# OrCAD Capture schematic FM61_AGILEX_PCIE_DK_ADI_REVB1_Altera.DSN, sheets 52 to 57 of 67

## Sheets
52 PWR - VCC -2: size Custom
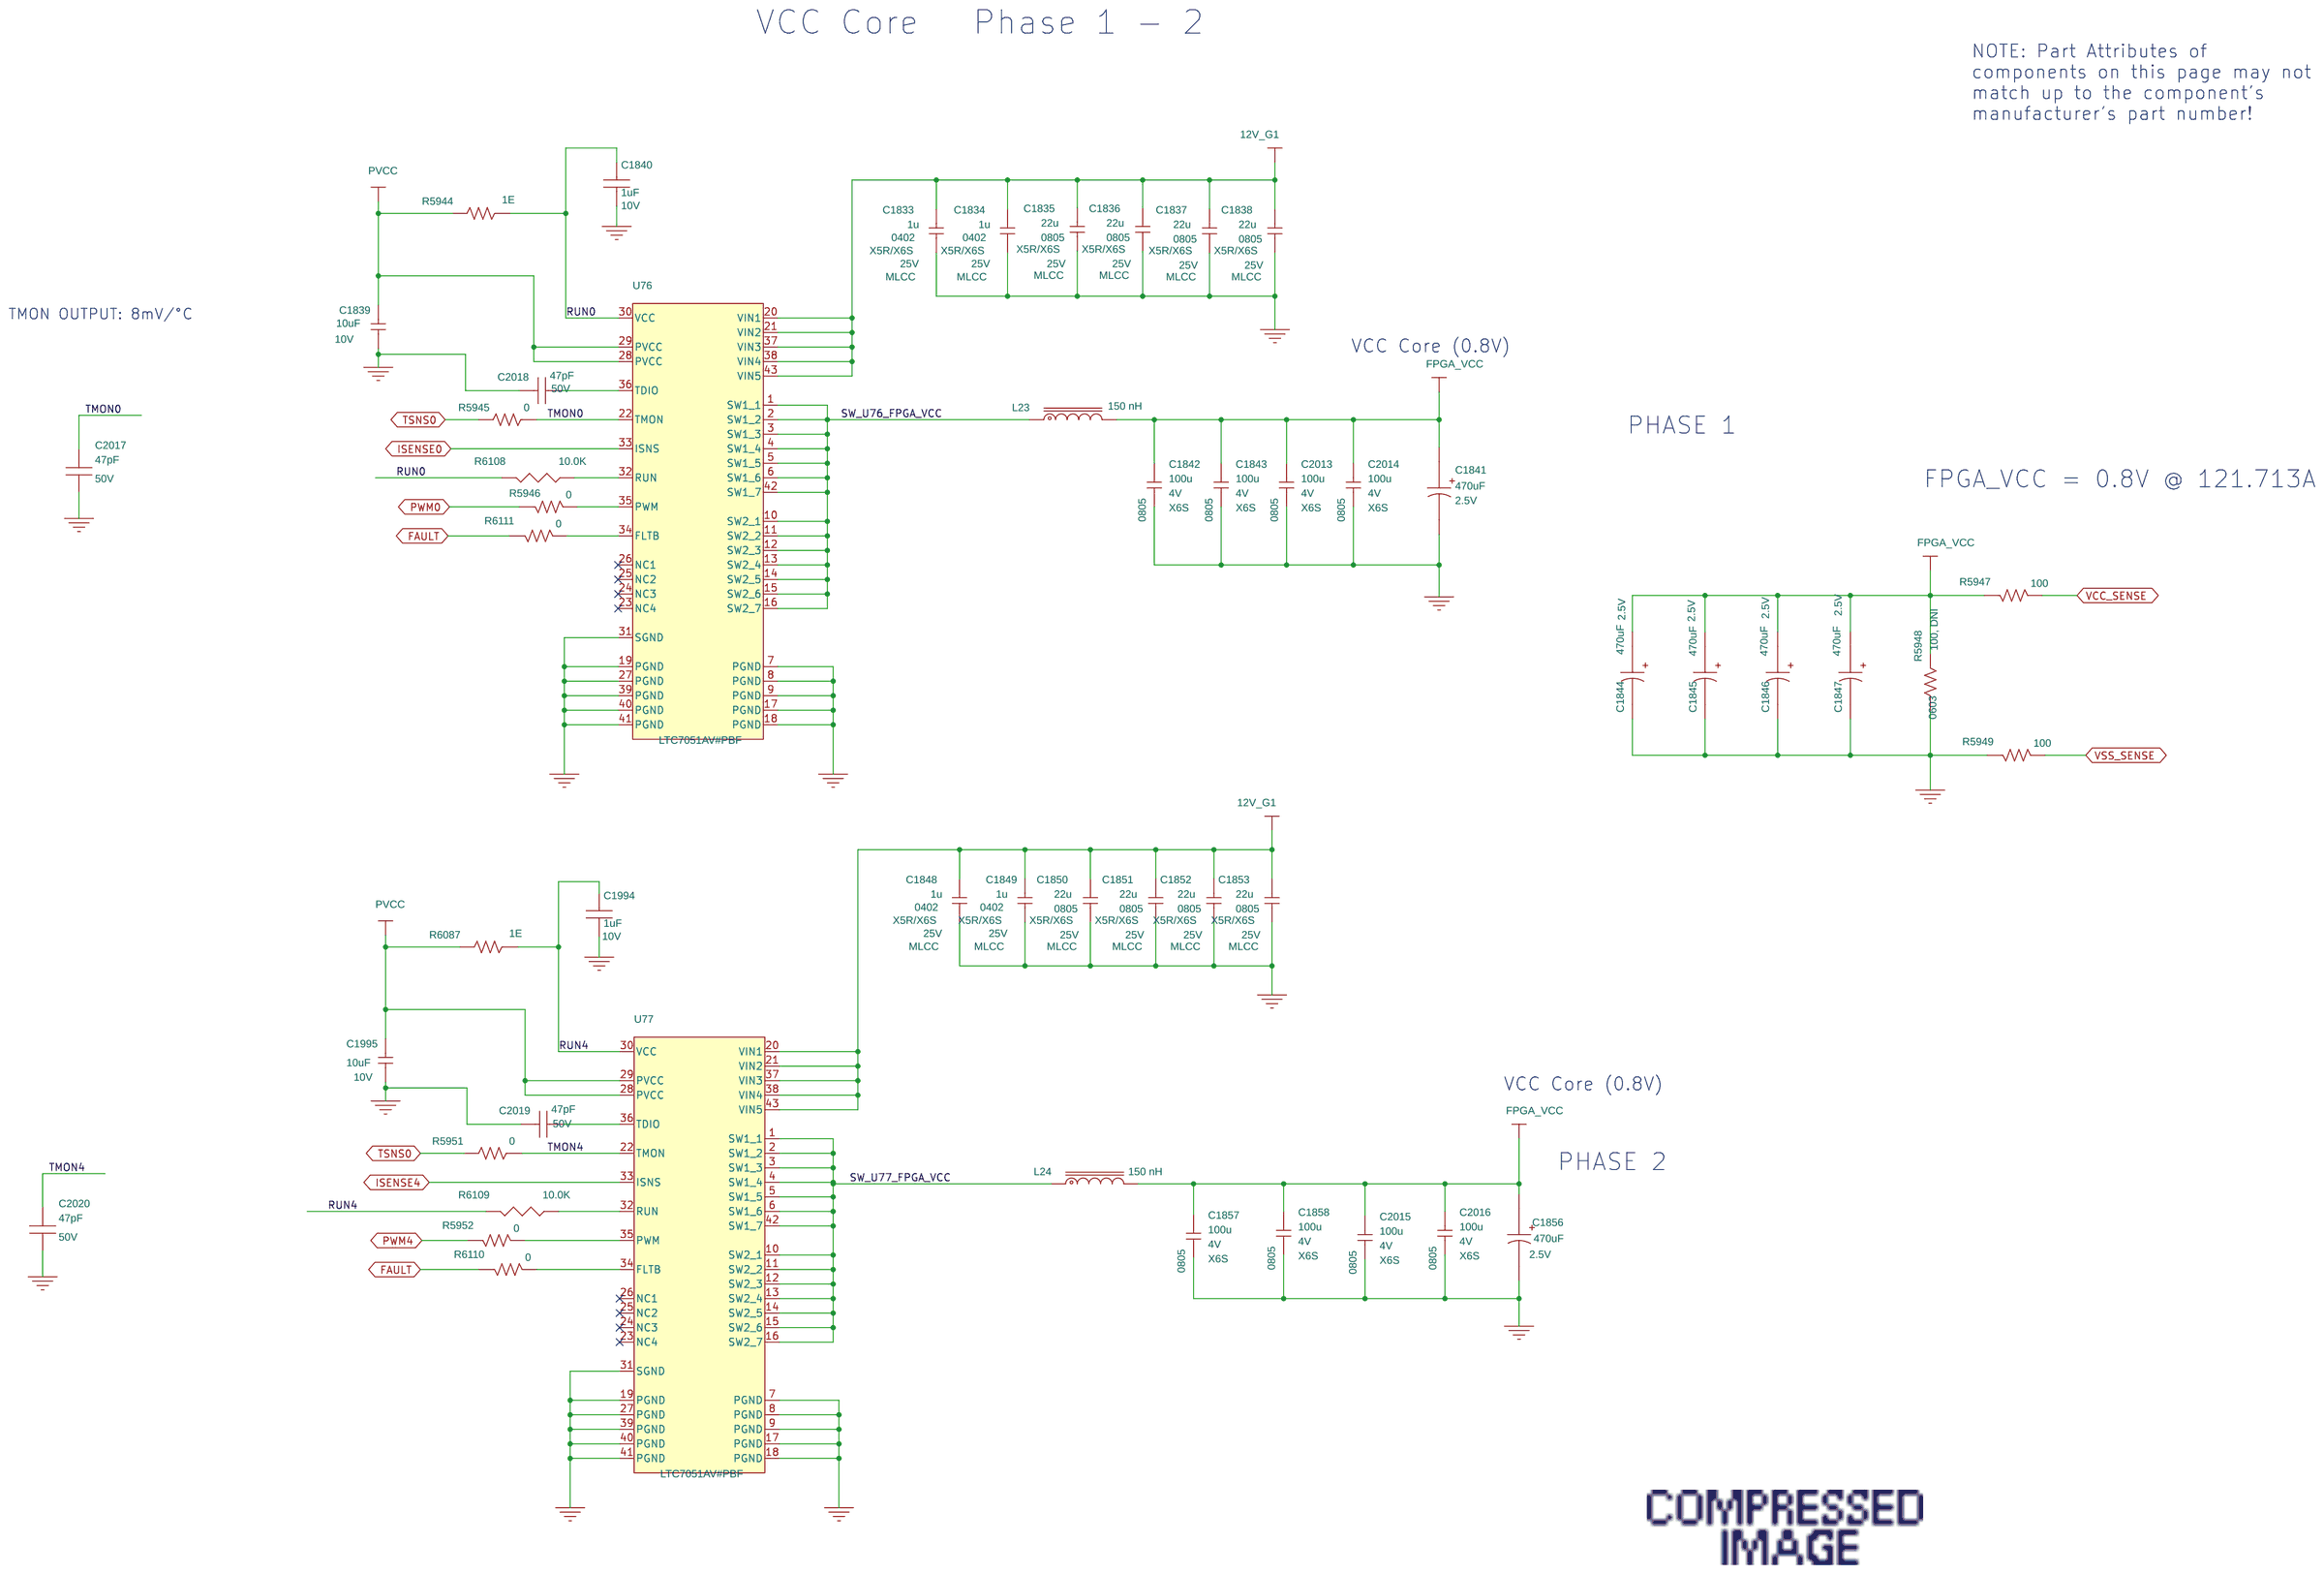
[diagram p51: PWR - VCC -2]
53 PWR - VCC -3: size Custom
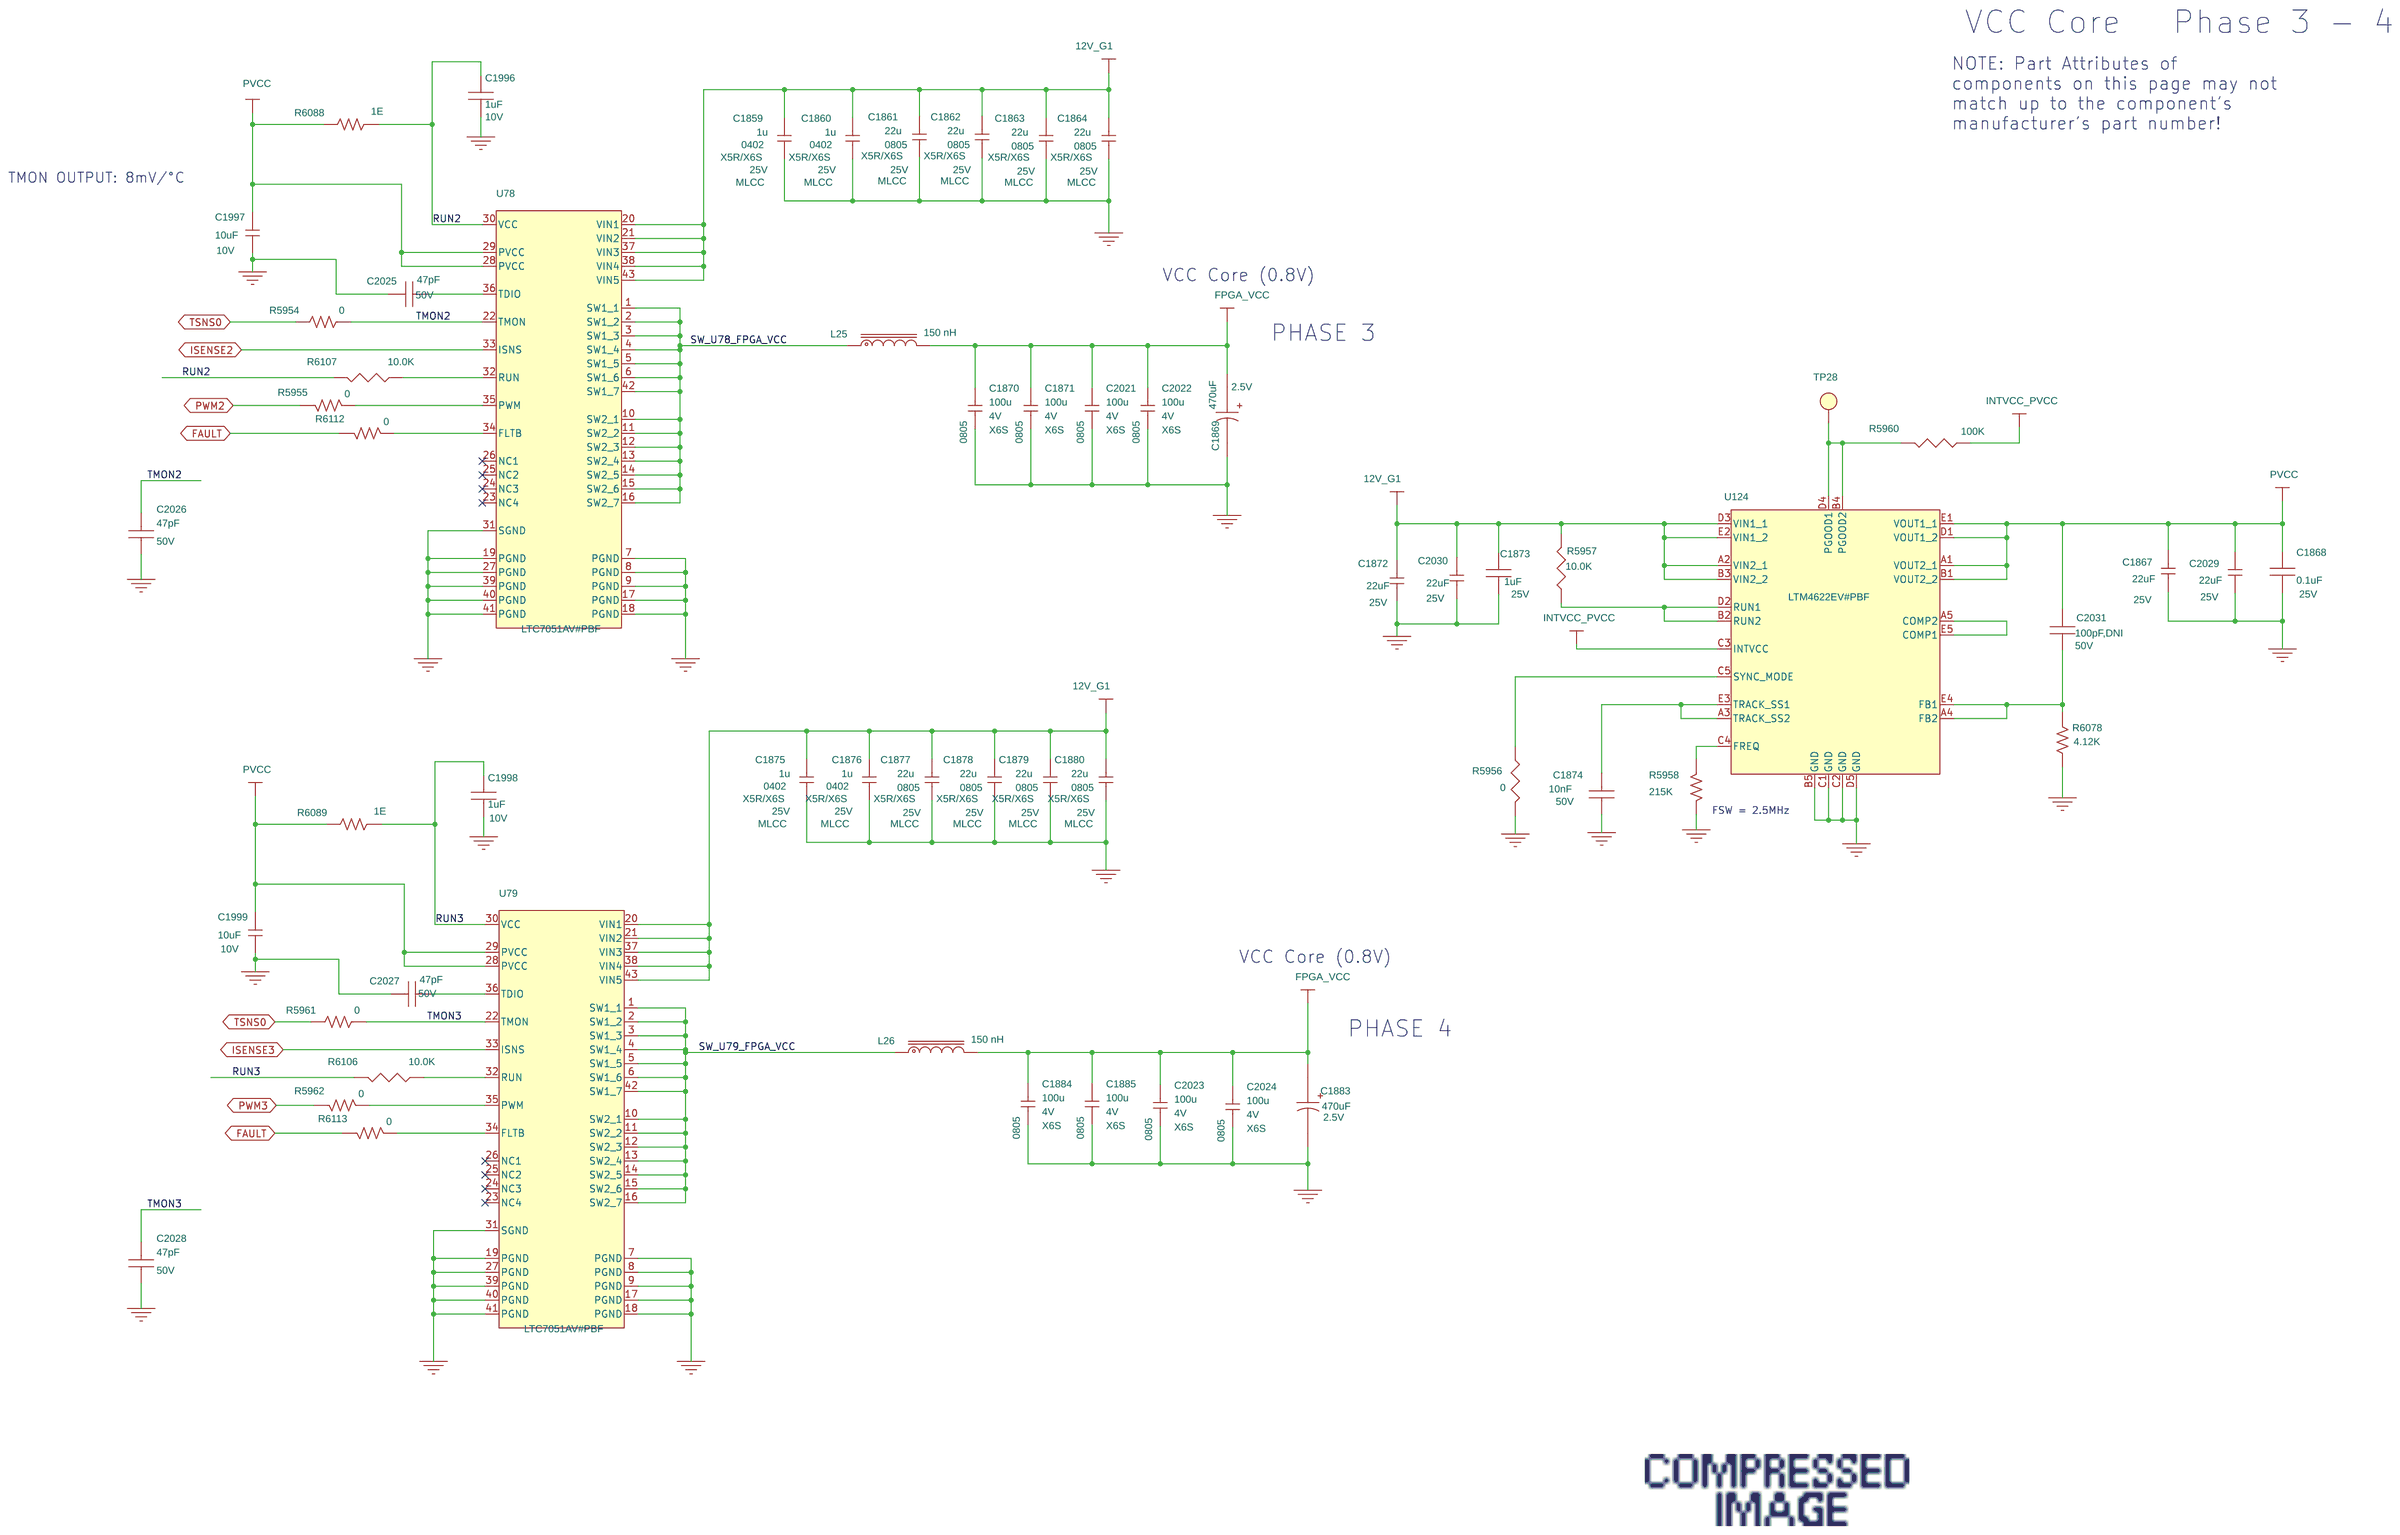
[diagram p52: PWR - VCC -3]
54 PWR - 1p8V: size Custom
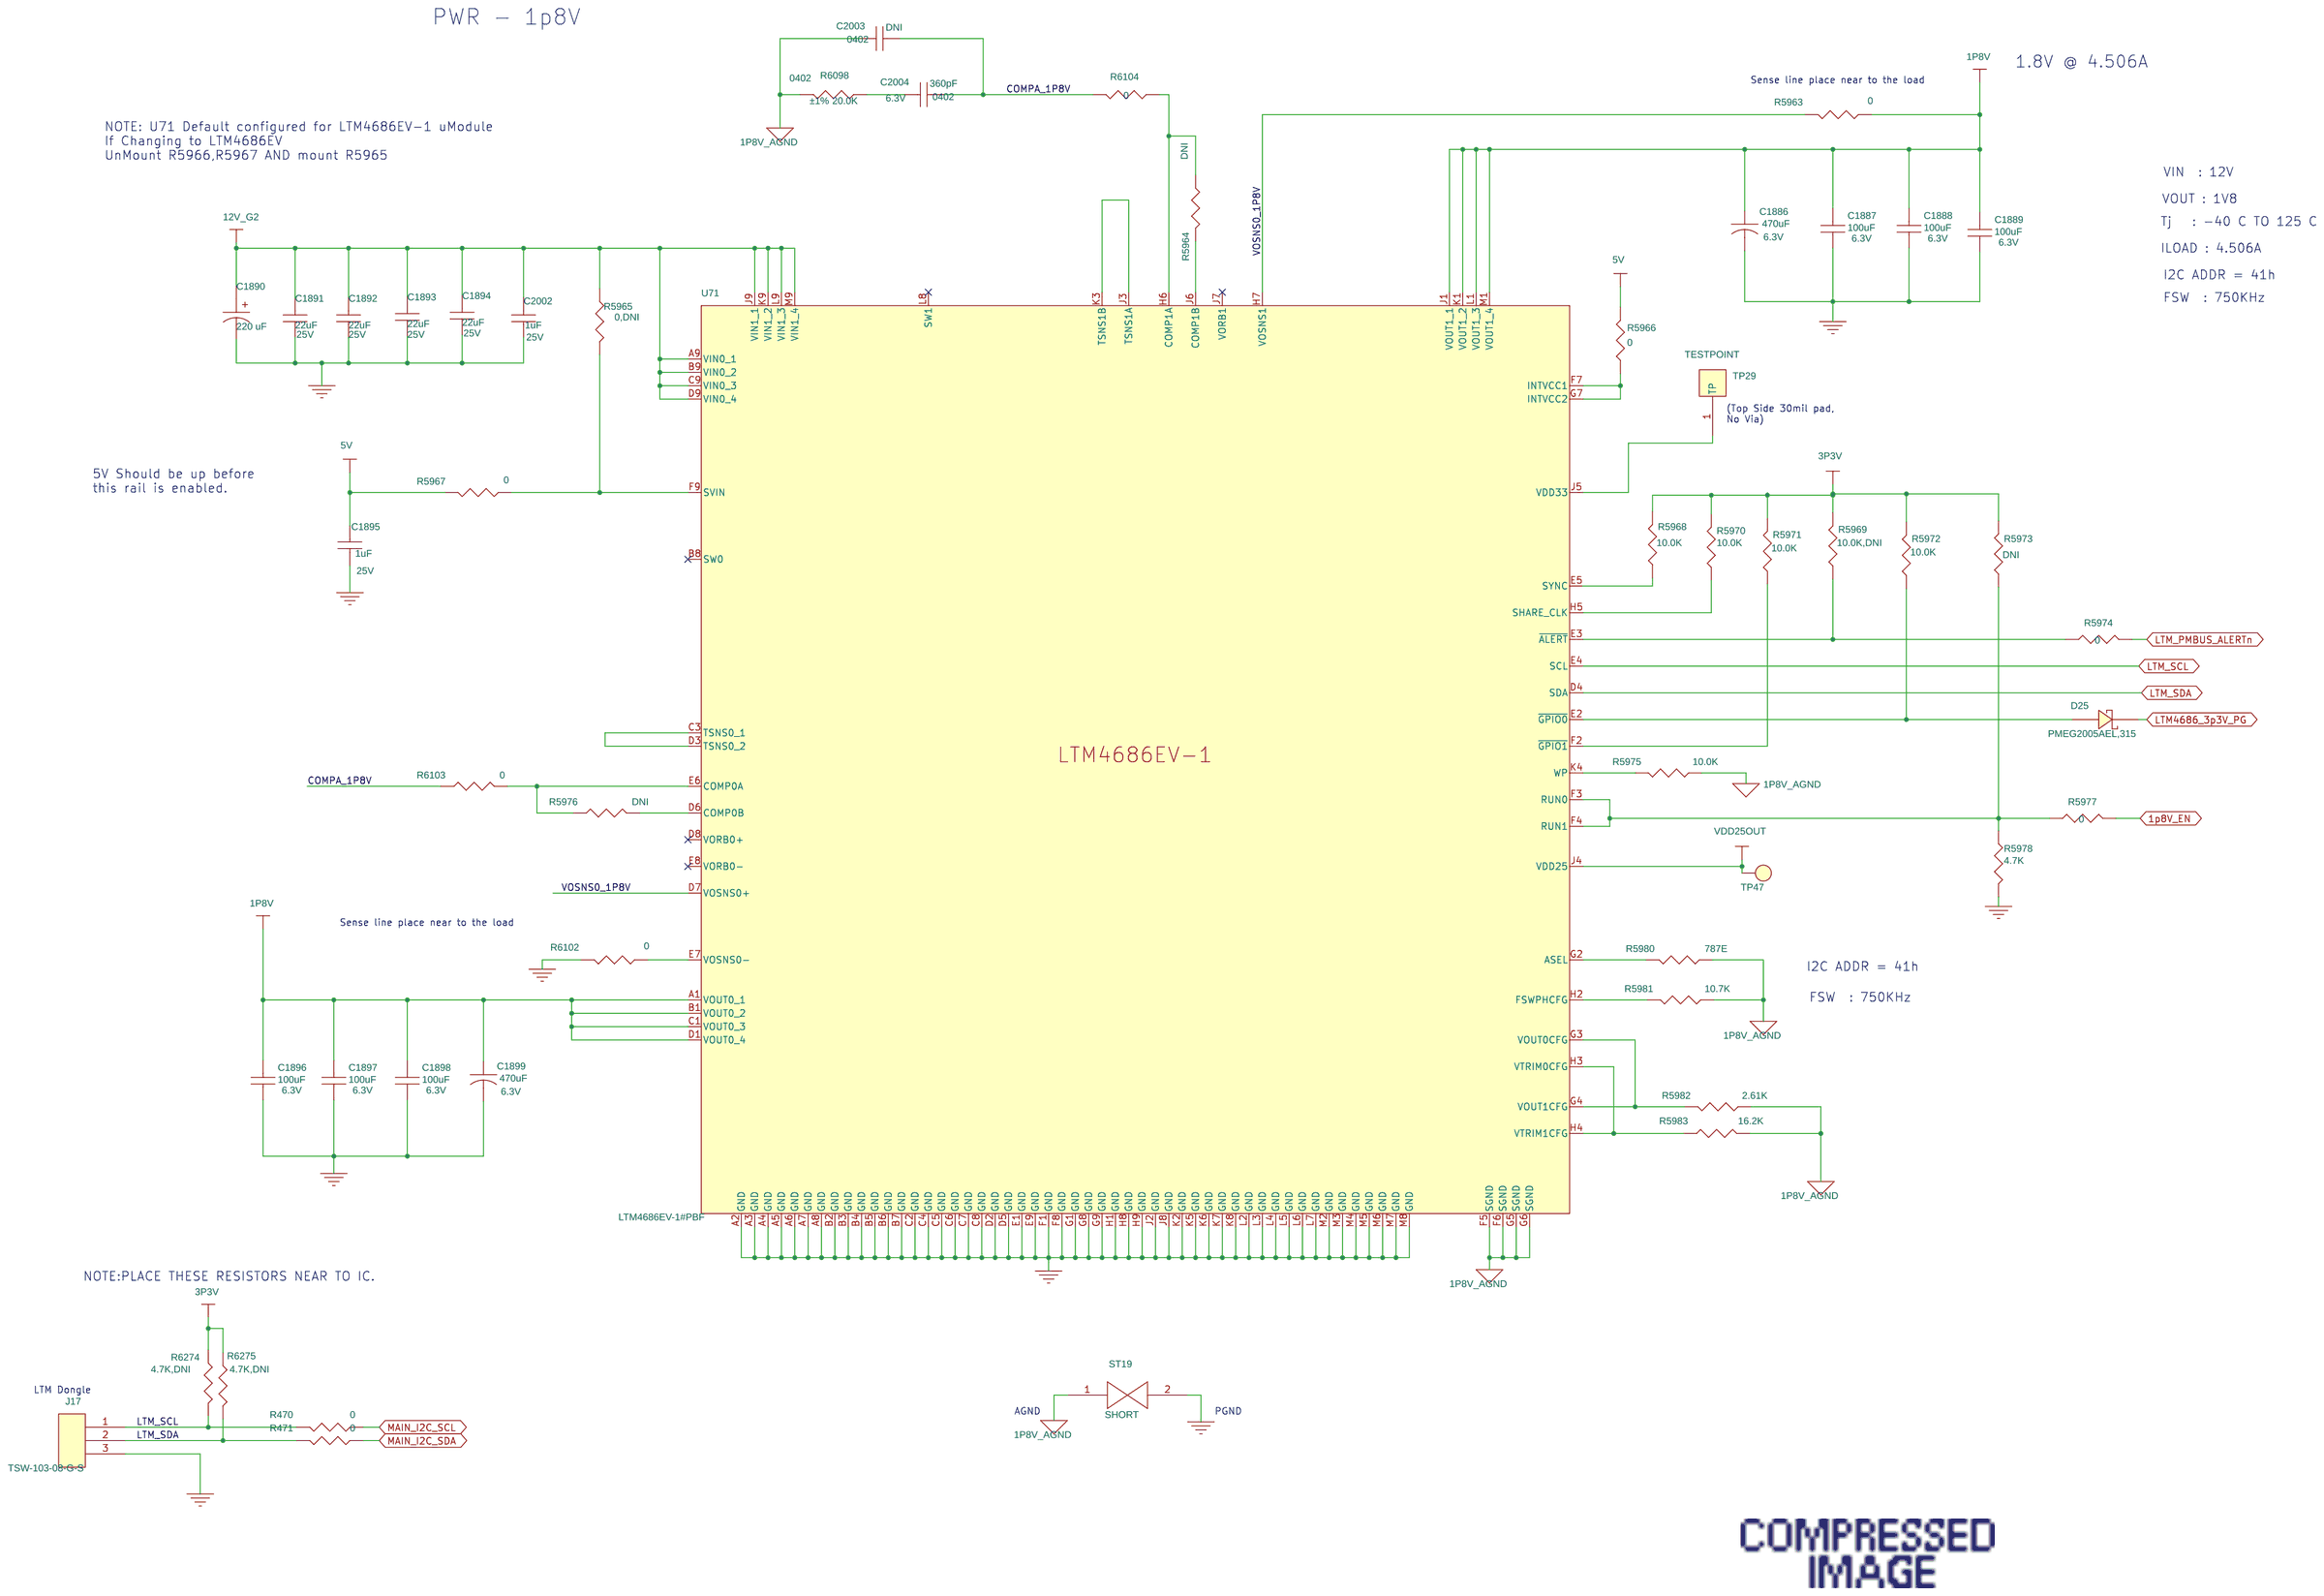
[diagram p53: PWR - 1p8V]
55 PWR - 0p8V_VCCL_SDM: size B
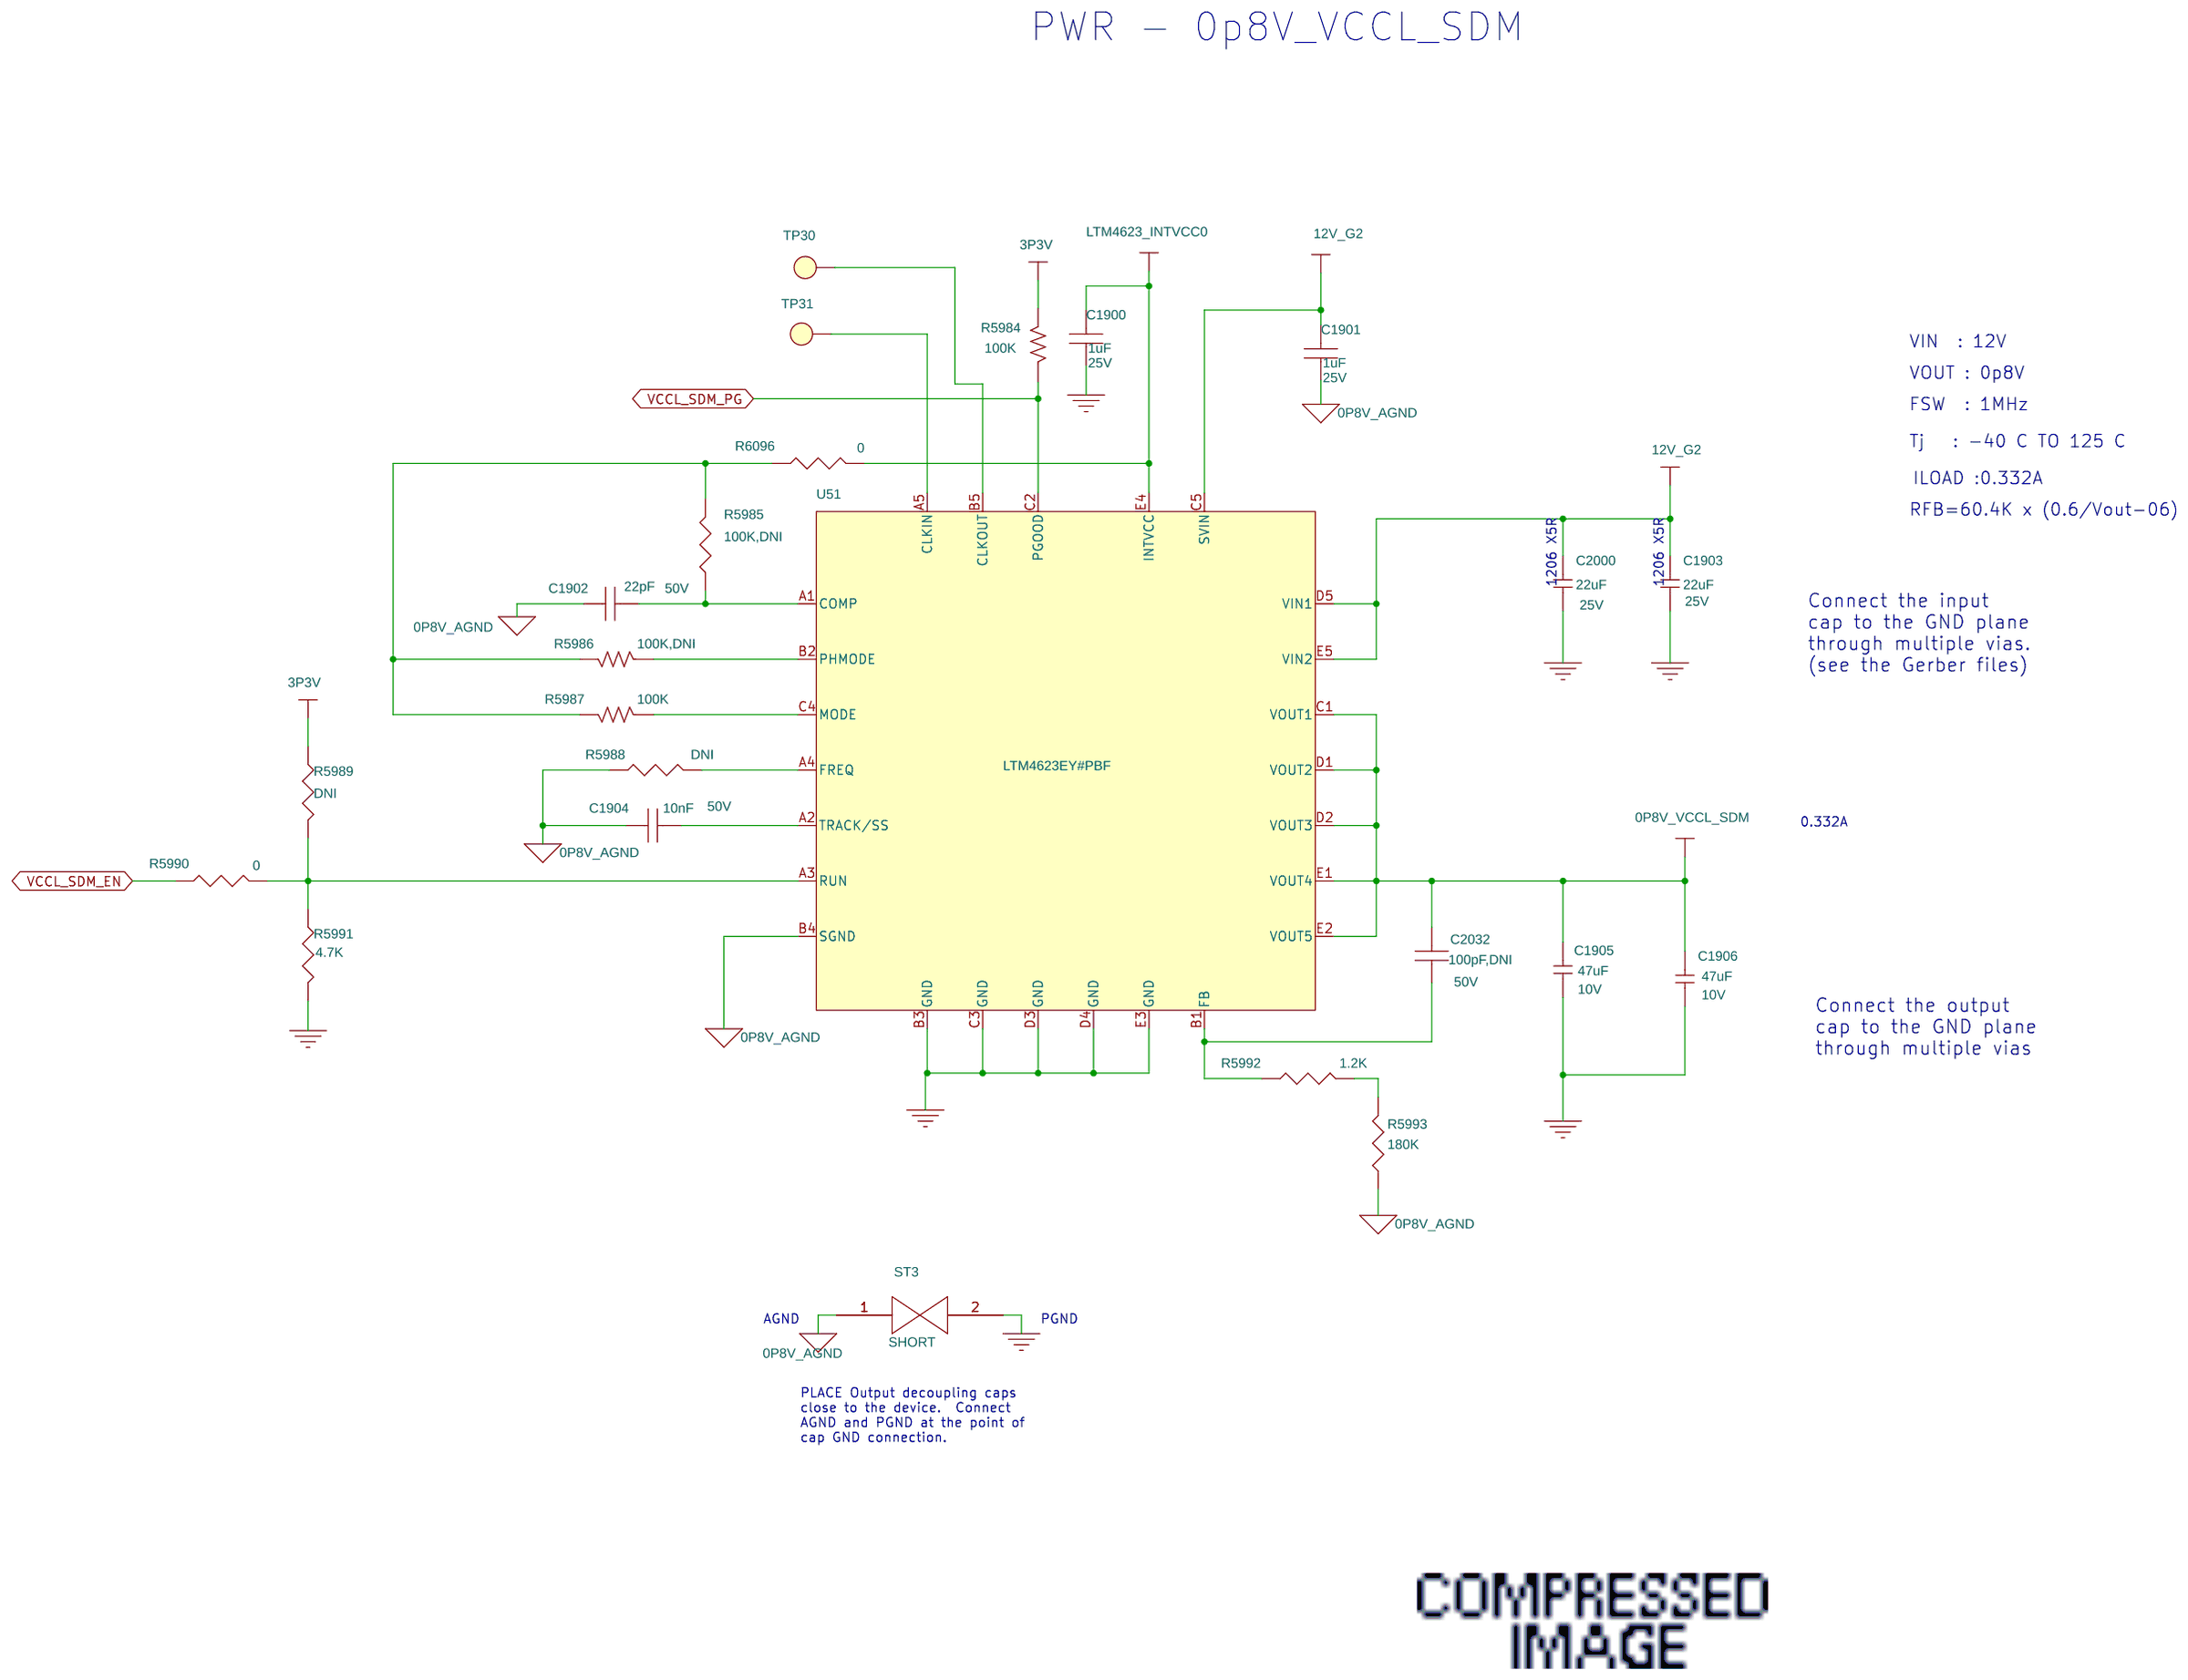
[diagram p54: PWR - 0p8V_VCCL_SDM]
56 PWR - 0p9V_VCCL_HPS: size B
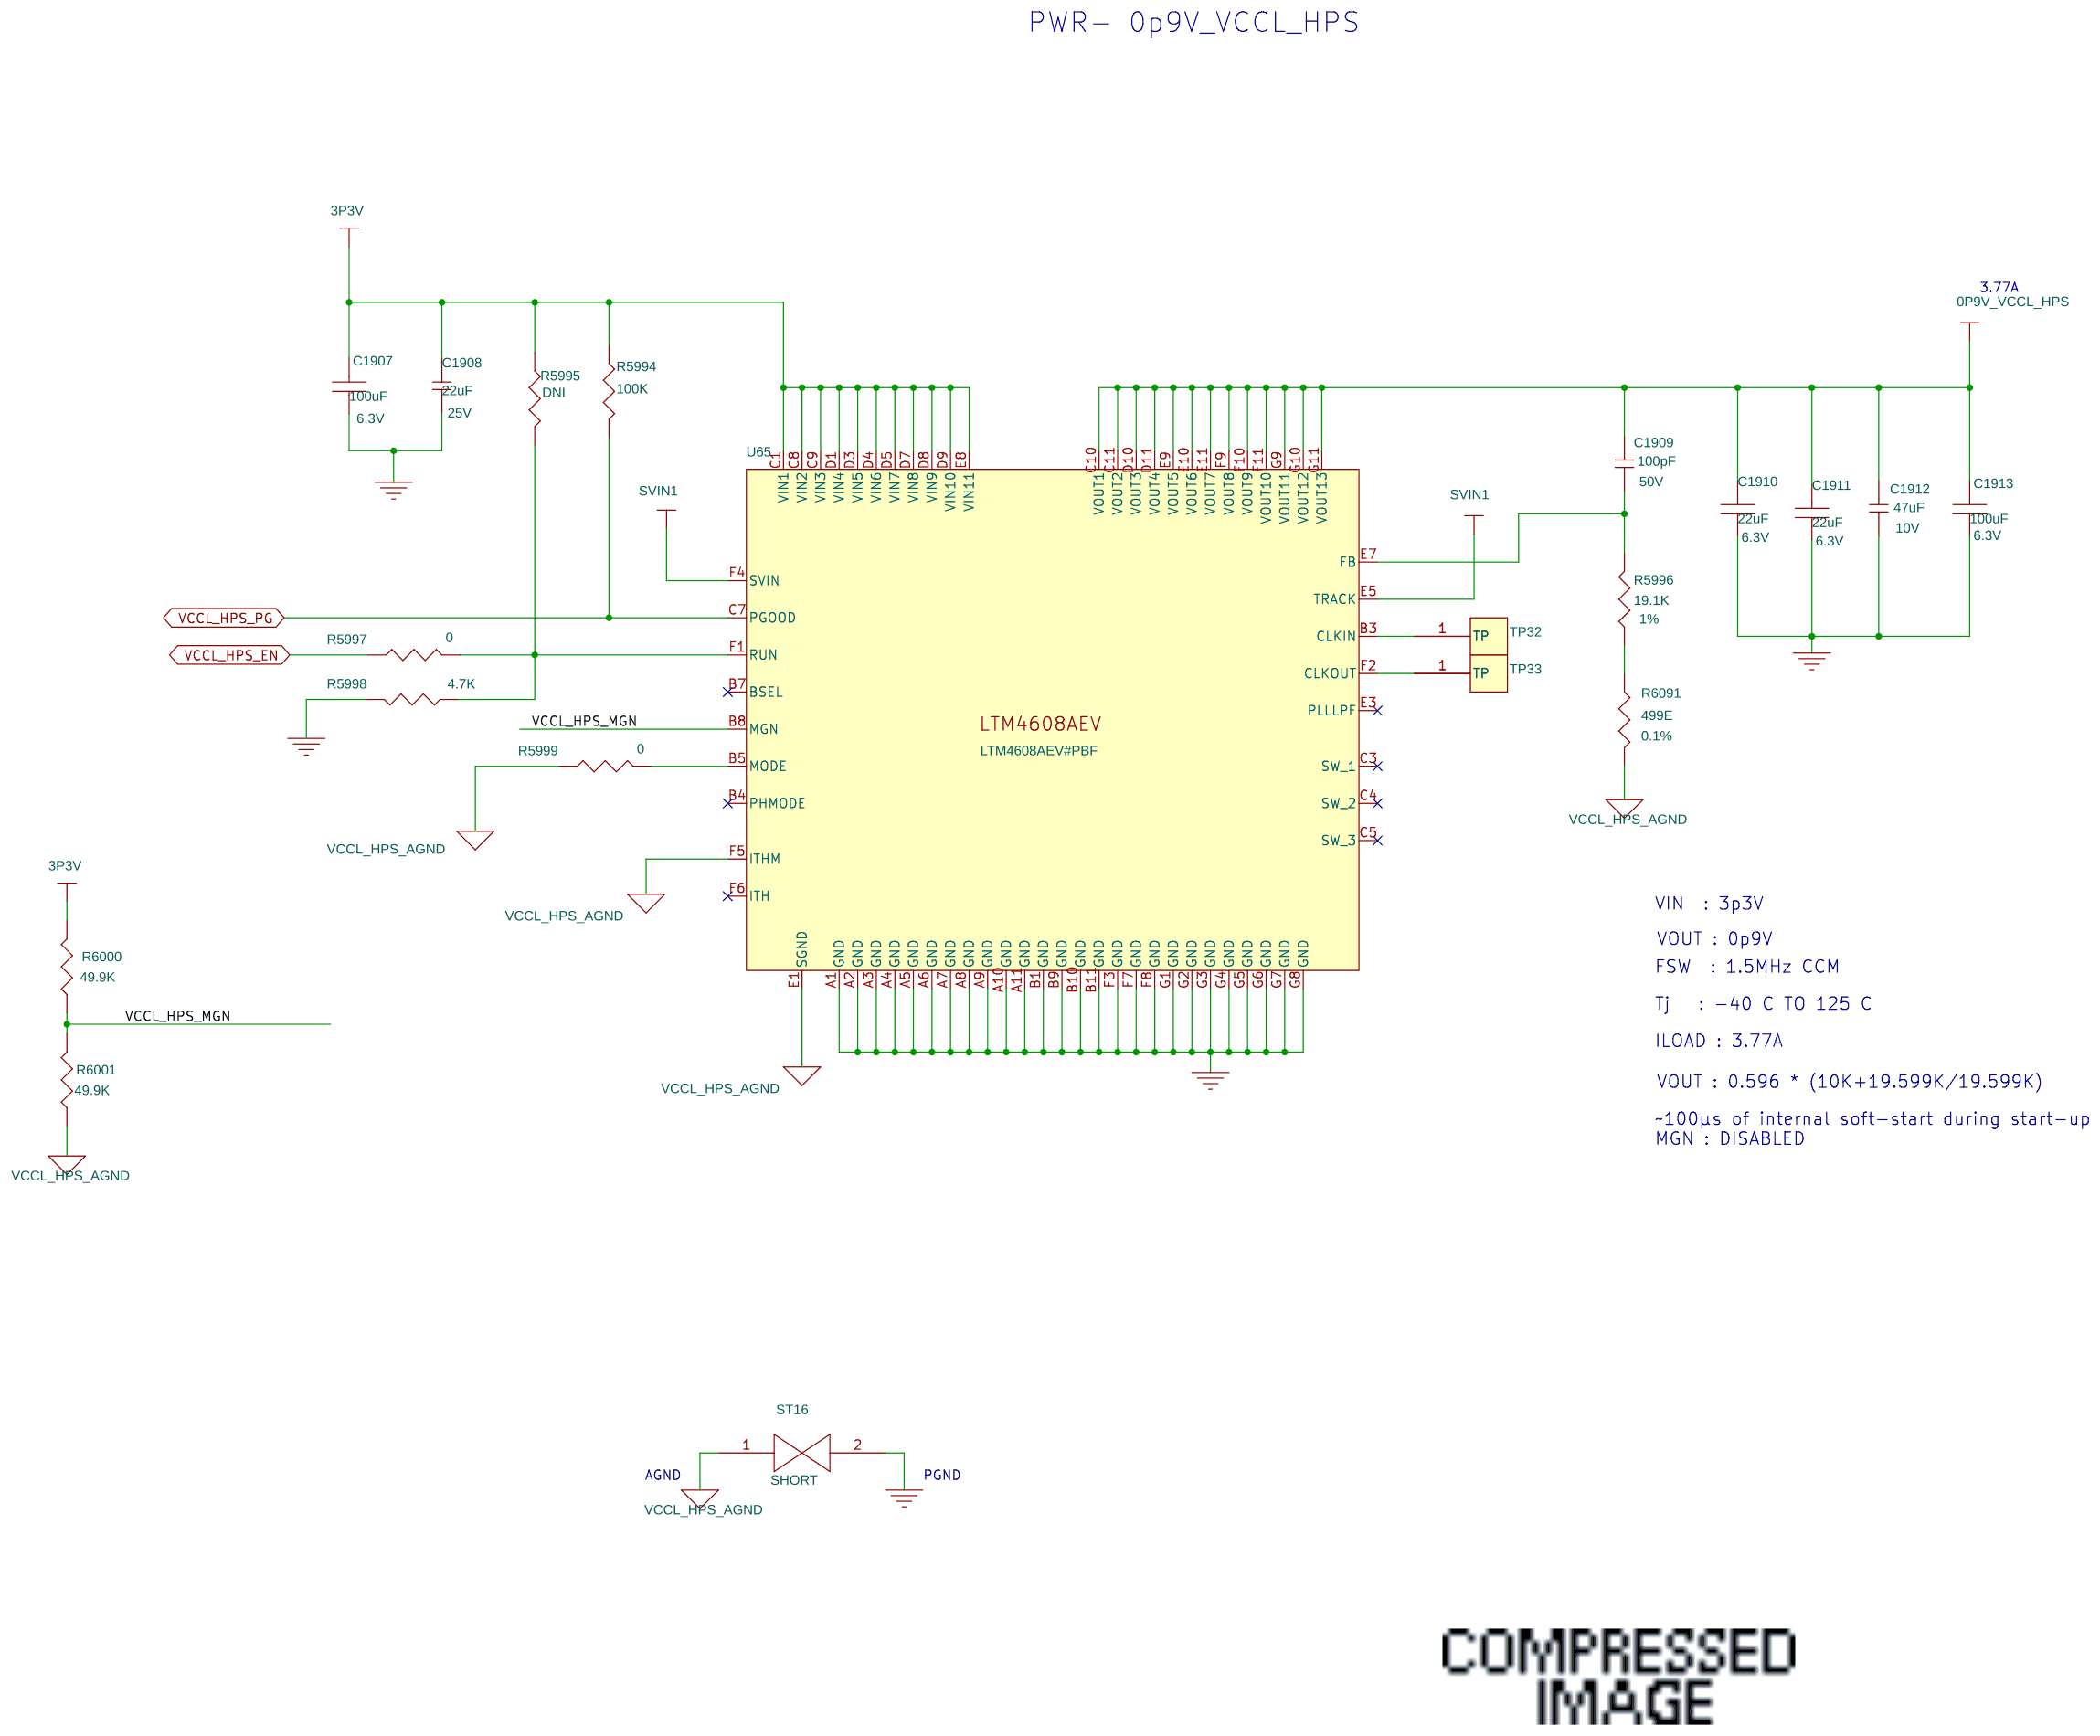
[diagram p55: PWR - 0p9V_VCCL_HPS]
57 PWR - IO_1p8V: size B
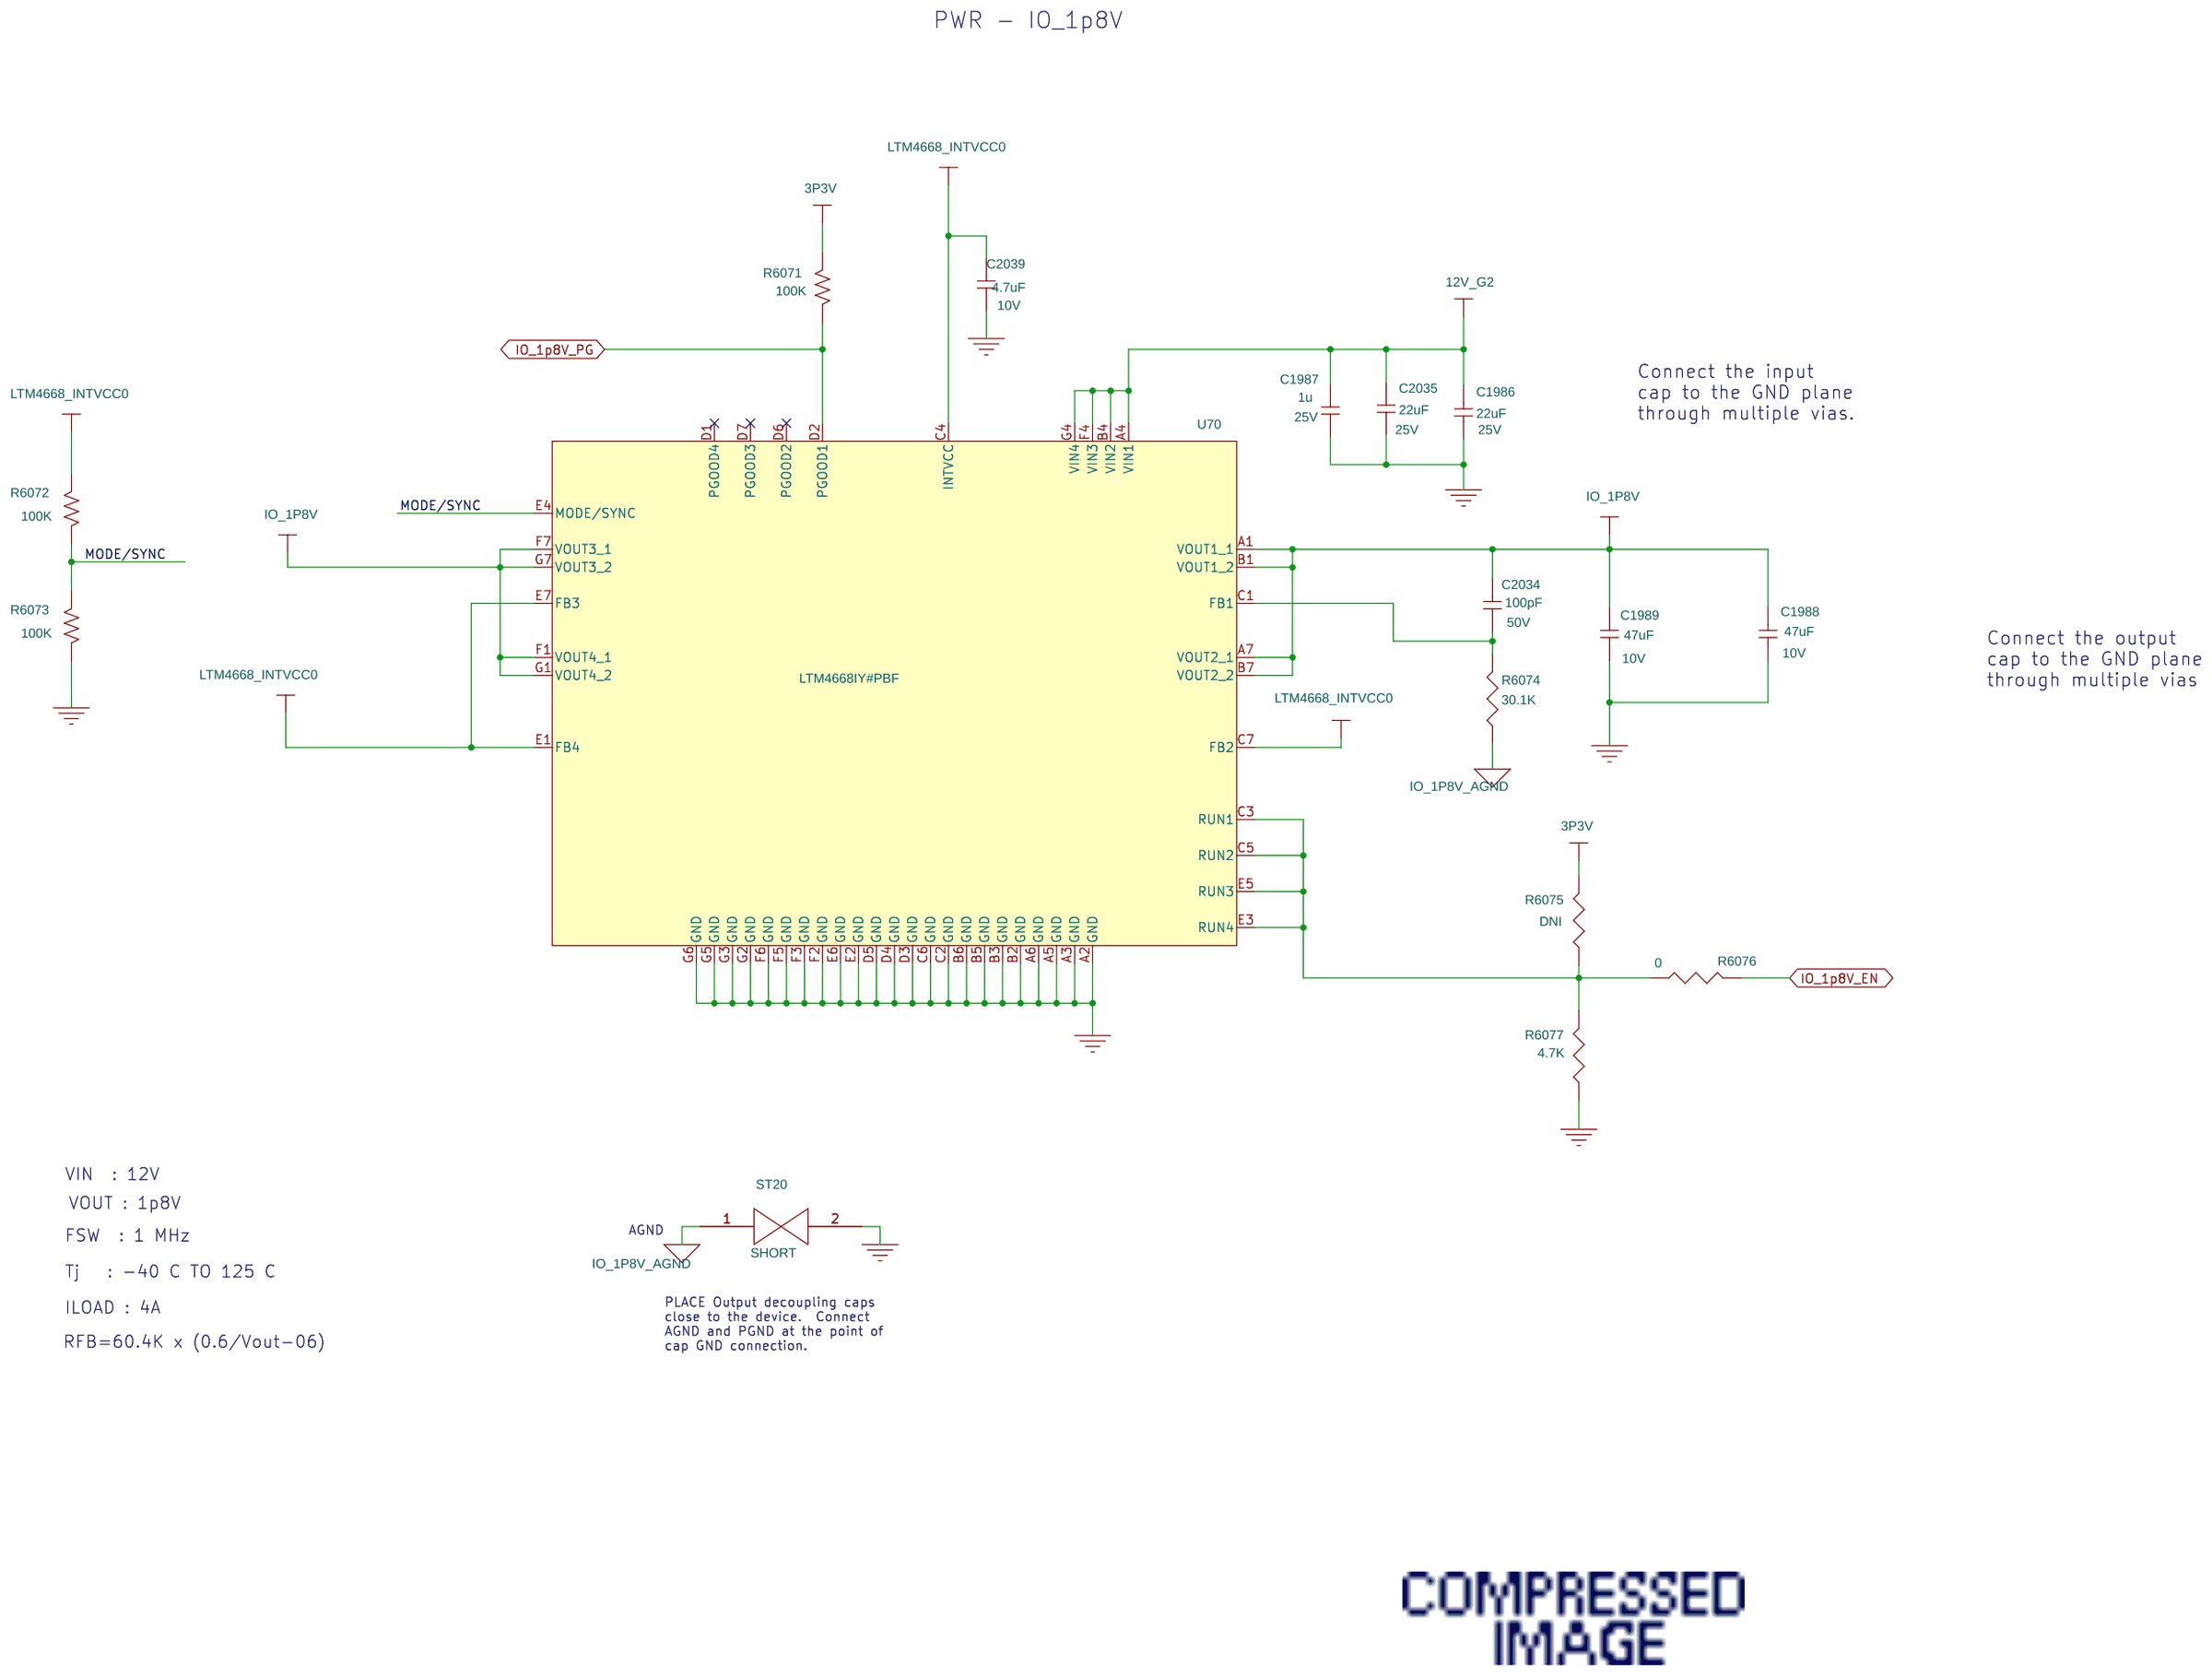
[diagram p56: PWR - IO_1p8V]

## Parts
sheet PWR - 0p8V_VCCL_SDM
C1900  1uF  [0402]
C1901  1uF  [0402]
C1902  22pF  [0402]
C1903  22uF  [1206]
C1904  10nF  [0402]
C1905  47uF  [C1206]
C1906  47uF  [C1206]
C2000  22uF  [1206]
C2032  100pF,DNI  [0402]
R5984  100K  [R0402]
R5985  100K,DNI  [0402]
R5986  100K,DNI  [R0402]
R5987  100K  [R0402]
R5988  DNI  [0402]
R5989  DNI  [0402]
R5990  0  [0402]
R5991  4.7K  [0402]
R5992  1.2K  [0402]
R5993  180K  [0402]
R6096  0  [0402]
ST3  SHORT  [SHORT]
TP30  TP, 0.016", Thru Hole  [30MIL_TP]
TP31  TP, 0.016", Thru Hole  [30MIL_TP]
U51  LTM4623EY#PBF  [BGA25C127P5X5_625X625X262]
sheet PWR - 0p9V_VCCL_HPS
C1907  100uF  [1206]
C1908  22uF  [1206]
C1909  100pF  [0402]
C1910  22uF  [0603]
C1911  22uF  [0603]
C1912  47uF  [1206]
C1913  100uF  [1206]
R5994  100K  [0402]
R5995  DNI  [0402]
R5996  19.1K  [0402]
R5997  0  [0402]
R5998  4.7K  [0402]
R5999  0  [0402]
R6000  49.9K  [0402]
R6001  49.9K  [0402]
R6091  499E  [0402]
ST16  SHORT  [SHORT]
TP32  TESTPOINT  [30mil_TP]
TP33  TESTPOINT  [30mil_TP]
U65  LTM4608AEV#PBF  [LGA68S127P7X11_900X1500X292]
sheet PWR - 1p8V
C1886  470uF  [D2E]
C1887  100uF  [1206]
C1888  100uF  [1206]
C1889  100uF  [1206]
C1890  220 uF  [CT7361-20]
C1891  22uF  [1206]
C1892  22uF  [1206]
C1893  22uF  [1206]
C1894  22uF  [1206]
C1895  1uF  [0402]
C1896  100uF  [1206]
C1897  100uF  [1206]
C1898  100uF  [1206]
C1899  470uF  [D2E]
C2002  1uF  [0402]
C2003  DNI  [0402]
C2004  360pF  [0402]
D25  PMEG2005AEL,315  [DIO_SOD882]
J17  TSW-103-08-G-S  [1x3_HDR_TH]
R470  0  [0402]
R471  0  [0402]
R5963  0  [0402]
R5964  DNI  [0402]
R5965  0,DNI  [0402]
R5966  0  [0402]
R5967  0  [0402]
R5968  10.0K  [0402]
R5969  10.0K,DNI  [0402]
R5970  10.0K  [0402]
R5971  10.0K  [0402]
R5972  10.0K  [0402]
R5973  DNI  [0402]
R5974  0  [0402]
R5975  10.0K  [0402]
R5976  DNI  [0402]
R5977  0  [0402]
R5978  4.7K  [0402]
R5980  787E  [0402]
R5981  10.7K  [0402]
R5982  2.61K  [0402]
R5983  16.2K  [0402]
R6098  20.0K  [0402]
R6102  0  [0402]
R6103  0  [0402]
R6104  0  [0402]
R6274  4.7K,DNI  [0402]
R6275  4.7K,DNI  [0402]
ST19  SHORT  [SHORT]
TP29  TESTPOINT  [30mil_TP]
TP47  TP, 0.016", Thru Hole  [30MIL_TP]
U71  LTM4686EV-1#PBF  [LGA108C127P9X12_1190X1600X192N]
sheet PWR - IO_1p8V
C1986  22uF  [1206]
C1987  1u  [capc1005x60l20l]
C1988  47uF  [C1206]
C1989  47uF  [C1206]
C2034  100pF  [0402]
C2035  22uF  [1206]
C2039  4.7uF  [0402]
R6071  100K  [R0402]
R6072  100K  [R0402]
R6073  100K  [R0402]
R6074  30.1K  [0402]
R6075  DNI  [0402]
R6076  0  [0402]
R6077  4.7K  [0402]
ST20  SHORT  [SHORT]
U70  LTM4668IY#PBF  [BGA49C80P7X7_625X625X230N]
sheet PWR - VCC -2
C1833  1u  [capc1005x60l20l]
C1834  1u  [capc1005x60l20l]
C1835  22u  [CAPC3216X135L50N]
C1836  22u  [CAPC3216X135L50N]
C1837  22u  [CAPC3216X135L50N]
C1838  22u  [CAPC3216X135L50N]
C1839  10uF  [0402]
C1840  1uF  [0402]
C1841  470uF  [CAPMP7343X300L130X240N_p079in]
C1842  100u  [CAPC2012X110L50L]
C1843  100u  [CAPC2012X110L50L]
C1844  470uF  [CAPMP7343X300L130X240N_p079in]
C1845  470uF  [CAPMP7343X300L130X240N_p079in]
C1846  470uF  [CAPMP7343X300L130X240N_p079in]
C1847  470uF  [CAPMP7343X300L130X240N_p079in]
C1848  1u  [capc1005x60l20l]
C1849  1u  [capc1005x60l20l]
C1850  22u  [CAPC3216X135L50N]
C1851  22u  [CAPC3216X135L50N]
C1852  22u  [CAPC3216X135L50N]
C1853  22u  [CAPC3216X135L50N]
C1856  470uF  [CAPMP7343X300L130X240N_p079in]
C1857  100u  [CAPC2012X110L50L]
C1858  100u  [CAPC2012X110L50L]
C1994  1uF  [0402]
C1995  10uF  [0402]
C2013  100u  [CAPC2012X110L50L]
C2014  100u  [CAPC2012X110L50L]
C2015  100u  [CAPC2012X110L50L]
C2016  100u  [CAPC2012X110L50L]
C2017  47pF  [0402]
C2018  47pF  [0402]
C2019  47pF  [0402]
C2020  47pF  [0402]
L23  150 nH  [ind_fp1008r-cus]
L24  150 nH  [ind_fp1008r-cus]
R5944  1E  [RESC1005X40L20L]
R5945  0  [RESC1005X40L20L]
R5946  0  [RESC1005X40L20L]
R5947  100  [RESC1005X40L20L]
R5948  100, DNI  [RESC1608X60L27N]
R5949  100  [RESC1005X40L20L]
R5951  0  [RESC1005X40L20L]
R5952  0  [RESC1005X40L20L]
R6087  1E  [RESC1005X40L20L]
R6108  10.0K  [0402]
R6109  10.0K  [0402]
R6110  0  [RESC1005X40L20L]
R6111  0  [RESC1005X40L20L]
U76  LTC7051AV#PBF  [ANALOG_LQFN-42P]
U77  LTC7051AV#PBF  [ANALOG_LQFN-42P]
sheet PWR - VCC -3
C1859  1u  [capc1005x60l20l]
C1860  1u  [capc1005x60l20l]
C1861  22u  [CAPC3216X135L50N]
C1862  22u  [CAPC3216X135L50N]
C1863  22u  [CAPC3216X135L50N]
C1864  22u  [CAPC3216X135L50N]
C1867  22uF  [1206]
C1868  0.1uF  [0402]
C1869  470uF  [CAPMP7343X300L130X240N_p079in]
C1870  100u  [CAPC2012X110L50L]
C1871  100u  [CAPC2012X110L50L]
C1872  22uF  [1206]
C1873  1uF  [0402]
C1874  10nF  [0402]
C1875  1u  [capc1005x60l20l]
C1876  1u  [capc1005x60l20l]
C1877  22u  [CAPC3216X135L50N]
C1878  22u  [CAPC3216X135L50N]
C1879  22u  [CAPC3216X135L50N]
C1880  22u  [CAPC3216X135L50N]
C1883  470uF  [CAPMP7343X300L130X240N_p079in]
C1884  100u  [CAPC2012X110L50L]
C1885  100u  [CAPC2012X110L50L]
C1996  1uF  [0402]
C1997  10uF  [0402]
C1998  1uF  [0402]
C1999  10uF  [0402]
C2021  100u  [CAPC2012X110L50L]
C2022  100u  [CAPC2012X110L50L]
C2023  100u  [CAPC2012X110L50L]
C2024  100u  [CAPC2012X110L50L]
C2025  47pF  [0402]
C2026  47pF  [0402]
C2027  47pF  [0402]
C2028  47pF  [0402]
C2029  22uF  [1206]
C2030  22uF  [1206]
C2031  100pF,DNI  [0402]
L25  150 nH  [ind_fp1008r-cus]
L26  150 nH  [ind_fp1008r-cus]
R5954  0  [RESC1005X40L20L]
R5955  0  [RESC1005X40L20L]
R5956  0  [0402]
R5957  10.0K  [0402]
R5958  215K  [0402]
R5960  100K  [0402]
R5961  0  [RESC1005X40L20L]
R5962  0  [RESC1005X40L20L]
R6078  4.12K  [0402]
R6088  1E  [RESC1005X40L20L]
R6089  1E  [RESC1005X40L20L]
R6106  10.0K  [0402]
R6107  10.0K  [0402]
R6112  0  [RESC1005X40L20L]
R6113  0  [RESC1005X40L20L]
TP28  TESTPOINT  [30MIL_TP]
U78  LTC7051AV#PBF  [ANALOG_LQFN-42P]
U79  LTC7051AV#PBF  [ANALOG_LQFN-42P]
U124  LTM4622EV#PBF  [LGA25C127P5X5_625X625X192N]

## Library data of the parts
C1873 C1895 C1900 C1901 = CAP: CAP - CER, 1UF, 25V, 10%, X5R, 0402; IPN: H29050-001; Item Num: P03-17662R; Lead Free Status: Yes; Manufacturer: TDK Electronics; Manufacturer Part Num: CGB2A1X5R1E105K033BC; Num Pins: 2; Part Class: CAPACITORS; RoHS Compliant: Yes; Voltage: 25V
C1902 = CAP: CAP CER 22PF 25V C0G/NP0 0402; AGILE_LINK: http://sj-agile9app/Agile/PLMServlet?action=OpenEmailObject&classid=10000&objid=257385742; CAPACITANCE: 12pF; IPN: J43675-001; Item Num: P03-15352R; LIFECYCLE_PHASE: Active; Lead Free Status: Lead Free; MFR_LIFECYCLE: Active; Manufacturer: Murata Electronics; Manufacturer Part Num: GRT1555C1E220JA02J; Num Pins: 2; PART_SUBCLASS: CAPACITORS; RATED_VOLTAGE: 50V; RoHS Compliant: RoHS Compliant; TOLERANCE: +/-5%
C1867 C1872 C1903 C1908 C1986 C2000 C2029 C2030 C2035 = Cap,_NP,_1206: CAP - CER, 22UF, 25V, 10%, X5R, 1206; IPN: K28232-001; Item Num: P03-17640R; Manufacturer: Murata; Manufacturer Part Num: GRM31CR61E226KE15L; Voltage: 25V
C1874 C1904 = CAP: CAP - CER, 10NF, 50V, +/-10%, X7R, 0402 SMD; IPN: A36096-100; Item Num: P03-16318R; Manufacturer: Murata; Manufacturer Part Num: GRM155R71H103KA88D; Price: 0; RoHS Compliant: RoHS Compliant; Voltage: 50V
C1905 C1906 C1912 C1988 C1989 = Cap,_NP,_1206: CAP - CER 47UF 10V 20% X5R 1206; IPN: K13655-001; Item Num: P03-17644R; Manufacturer: TDK Electronics; Manufacturer Part Num: C3216X5R1A476M160AB; Voltage: 10V
C2031 C2032 = CAP: CAPC,C0G,0402,100.000PF,50.000V,+/-5%; CAPACITANCE: 100pF; Dielectric: X7R; IPN: A36095-026; IPN No: A36095-026; Item Num: P03-XXXXXR; LIFECYCLE_PHASE: Active; Lead Free Status: Lead Free; Manufacturer: AVX; Manufacturer Part Num: UMK105CG101JV-F; Num Pins: 2; Part Class: CAPACITORS; RATED_VOLTAGE: 50V; RoHS Compliant: RoHS Compliant; Tolerance: 10%; Voltage: 50V
R5984 R5987 R6071-R6073 = Resistor,_0402: RES,100K OHMS,1.0%,1/16W,0402; IPN: E86804-001; Item Num: P02-11386R; Manufacturer: Panasonic; Manufacturer Part Num: ERJ-2RKF1003X; POWER: 1/16W; TOLERANCE: +/-1%
R5985 = RESISTOR: RES,100K OHMS,1.0%,1/16W,0402; AGILE_LINK: http://sj-agile9app/Agile/PLMServlet?action=OpenEmailObject&classid=10000&objid=146932246; IPN: E86804-001; Item Num: P02-11386R; LIFECYCLE_PHASE: Active; MFR_LIFECYCLE: Active; Manufacturer: Panasonic; Manufacturer Part Num: ERJ-2RKF1003X; Num Pins: 2; PART_SUBCLASS: RESISTORS; POWER: 1/16W; RESISTANCE: 100K; RoHS Compliant: RoHS Compliant; TOLERANCE: +/-1%
R5986 = Resistor,_0402: RES,100K OHMS,1.0%,1/16W,0402; IPN: E86804-001; Item Num: P02-11386R; Manufacturer: Panasonic; Manufacturer Part Num: ERJ-2RKF1003X; POWER: 1/16W; RESISTANCE: 100K; TOLERANCE: +/-1%
R5988 = RESISTOR: RES ZERO OHM 1/16W 5% 0402 SMD; Altera Part No.: P02-14020R; IPN: H30887-001; Item Num: P02-14020R; LIFECYCLE_PHASE: Active; Lead Free Status: No; MFR_LIFECYCLE: Active; Manufacturer: Panasonic; Manufacturer Part Num: ERJ-2GE0R00X; Num Pins: 2; PART_SUBCLASS: RESISTORS; POWER: 1/16W; Part Class: RESISTORS; Price: 0; RESISTANCE: 0; RoHS Compliant: RoHS Compliant; Tolerance: +/-5%
R5964 R5965 R5973 R5976 R5989 R5995 R6075 = RESISTOR: RES ZERO OHM 1/16W 5% 0402 SMD; Altera Part No.: P02-14020R; IPN: H30887-001; Item Num: P02-14020R; Lead Free Status: No; Manufacturer: Panasonic; Manufacturer Part Num: ERJ-2GE0R00X; Num Pins: 2; Part Class: RESISTORS; Price: 0; RoHS Compliant: Yes; Tolerance: 5%
R5990 R6076 = RESISTOR: RES ZERO OHM 1/16W 5% 0402 SMD; Altera Part No.: P02-14020R; IPN: H30887-001; Item Num: P02-14020R; LIFECYCLE_PHASE: Active; Lead Free Status: No; MFR_LIFECYCLE: Active; Manufacturer: Panasonic; Manufacturer Part Num: ERJ-2GE0R00X; Num Pins: 2; PART_SUBCLASS: RESISTORS; POWER: 1/16W; Part Class: RESISTORS; RoHS Compliant: RoHS Compliant; Tolerance: +/-5%
R5978 R5991 R5998 R6077 R6274 R6275 = RESISTOR: RES 4.7K OHM 1/16W 5% 0402 SMD; IPN: H30885-001; Item Num: P02-14032R; Lead Free Status: No; Manufacturer: Panasonic; Manufacturer Part Num: ERJ-2GEJ472X; Manufacturer's Part No.: ERJ-2GEJ472X; Num Pins: 2; Part Class: RESISTORS; Price: 0; RoHS Compliant: Yes
R5992 = RESISTOR: RES SMD 1.2K OHM 1% 1/10W 0402; Altera Part No.: P02-14020R; IPN: J99186-001; Item Num: P02-14020R; LIFECYCLE_PHASE: Active; Lead Free Status: No; MFR_LIFECYCLE: Active; Manufacturer: Panasonic; Manufacturer Part Num: ERJ-2RKF1201X; Manufaturer: Panasonic; Num Pins: 2; PART_SUBCLASS: RESISTORS; POWER: 1/16W; Part Class: RESISTORS; Part Number: ERJ-2RKF1201X; Price: 0; RESISTANCE: 0; RoHS Compliant: RoHS Compliant; Tolerance: +/-5%
R5993 = RES: RES SMD 180K OHM 1% 1/10W 0402; IPN: K69549-001; Item Num: P02-15992R; Manufacturer: yageo; Manufacturer Part Num: RT0402BRD07180KL; Package: SMD; Part Class: RESISTORS; Type: Resistor
R5963 R5966 R5967 R5974 R5977 R5997 R5999 R6096 R6102-R6104 = RESISTOR: RES ZERO OHM 1/16W 5% 0402 SMD; Altera Part No.: P02-14020R; IPN: H30887-001; Item Num: P02-14020R; Lead Free Status: No; Manufacturer: Panasonic; Manufacturer Part Num: ERJ-2GE0R00X; Num Pins: 2; Part Class: RESISTORS; RoHS Compliant: Yes; Tolerance: 5%
ST3 ST16 ST19 ST20 = SHORT
TP28 TP30 TP31 TP47 = TP,_0.016_,_Thru_Hole
U51 = LTM4623EY#PBF: IPN: K15502-001
C1907 C1913 = CAP: CAP CER 100UF 6.3V X6T 1206; AGILE_LINK: http://sj-agile9app/Agile/PLMServlet?action=OpenEmailObject&classid=10000&objid=257560276; IPN: H65271-004; Item Num: P03-18002R; LIFECYCLE_PHASE: Active; Lead Free Status: Lead Free; MFR_LIFECYCLE: Active; Manufacturer: Murata; Manufacturer Part Num: GRM31CD80J107ME39L; Num Pins: 2; PART_SUBCLASS: CAPACITORS; RATED_VOLTAGE: 6.3V; RoHS Compliant: RoHS Compliant; TOLERANCE: 20%; Temperature Coefficient: X6T; Voltage: 6.3V
C1909 C2034 = Cap,_NP,_0402: CAPC,C0G,0402,100.000PF,50.000V,+/-5%; IPN: A36095-026; Item Num: P03-11677R; Manufacturer: Murata; Manufacturer Part Num: UMK105CG101JV-F; RATED_VOLTAGE: 50V; Voltage: 50V
C1910 C1911 = CAP: CAP CER 22UF 6.3V X6S 0603; AGILE_LINK: http://sj-agile9app/Agile/PLMServlet?action=OpenEmailObject&classid=10000&objid=257560276; IPN: H63299-001; Item Num: P03-17963R; LIFECYCLE_PHASE: Active; Lead Free Status: Not Lead Free; MFR_LIFECYCLE: Active; Manufacturer: Murata; Manufacturer Part Num: GRM188C80J226ME15D; Num Pins: 2; PART_SUBCLASS: CAPACITORS; RATED_VOLTAGE: 6.3V; RoHS Compliant: RoHS Compliant; TOLERANCE: 20%; Temperature Coefficient: X6S; Voltage: 6.3V
R5960 R5994 = RESISTOR: RES,100K OHMS,1.0%,1/16W,0402; IPN: E86804-001; Item Num: P02-11386R; Lead Free Status: No; Manufacturer: Panasonic; Manufacturer Part Num: ERJ-2RKF1003X; Num Pins: 2; POWER: 1/16W; Part Class: Resistors; Price: 0; RoHS Compliant: Yes; TOLERANCE: +/-1%
R5996 = RES: RES SMD 19.1K OHM 1% 1/10W 0402; IPN: A93548-019; Item Num: P02-15992R; Manufacturer: Panasonic Electronic Components; Manufacturer Part Num: ERJ-2RKF1912X; Package: SMD; Part Class: RESISTORS; Tolerance: 1%; Type: Resistor
R6000 R6001 = RESISTOR: RES SMD 49.9KOHM 0.1% 1/16W 0402; IPN: C79651-037; Item Num: P02-17979R; Manufacturer: Panasonic; Manufacturer Part Num: ERA-2AEB4992X
R6091 = RESISTOR: RES SMD 499 OHM 0.1% 1/16W 0402; IPN: E59511-001; Item Num: P02-14007R; Lead Free Status: No; Manufacturer: STACKPOLE; Manufacturer Part Num: RNCF0402BTE499R; Num Pins: 2; Part Class: RESISTORS; Part Number: RT0402BRE07499RL; Price: 0; RoHS Compliant: Yes; Tolerance: 0.1%
TP29 TP32 TP33 = TESTPOINT
U65 = LTM4608AEV#PBF_V1: IPN: E78633-001
C1886 C1899 = PCAP: CAP TANT POLY 470UF 6.3V 2917; ESR: 10mOHM; IPN: K49922-001; Item Num: P03-18023R; LIFECYCLE_PHASE: Active; Lead Free Status: Lead Free; MFR_LIFECYCLE: Active; Manufacturer: Panasonic; Manufacturer Part Num: 6TPF470MAH; Num Pins: 2; PART_SUBCLASS: CAPACITORS; RATED_VOLTAGE: 6.3V; RoHS Compliant: RoHS Compliant; Working Voltage: 6.3V
C1887-C1889 C1896-C1898 = CAP: CAP CER 100UF 6.3V X6T 1206; AGILE_LINK: http://sj-agile9app/Agile/PLMServlet?action=OpenEmailObject&classid=10000&objid=257560276; IPN: H65271-004; Item Num: P03-18002R; LIFECYCLE_PHASE: Active; Lead Free Status: Lead Free; MFR_LIFECYCLE: Active; Manufacturer: Murata; Manufacturer Part Num: GRM31CD80J107ME39L; Num Pins: 2; PART_SUBCLASS: CAPACITORS; RATED_VOLTAGE: 6.3V; RoHS Compliant: RoHS Compliant; TOLERANCE: 20%; Temperature Coefficient: X6T
C1890 = TCN4227M025R0100: IPN: M75353-001
C1891-C1894 = CAP: CAP - CER, 22UF, 25V, 10%, X5R, 1206; Agile Part Number: P03-17640R; IPN: K28232-001; Item Num: P03-17640R; Lead Free Status: Yes; Manufacturer: Murata; Manufacturer Part Num: GRM31CR61E226KE15L; Num Pins: 2; Part Class: Capacitors; Price: 0; RoHS Compliant: Yes; Voltage: 25V
C2002 = CAP: CAP - CER, 1UF, 25V, 10%, X5R, 0402; IPN: H29050-001; IPN No: H29050-001; Item Num: P03-17662R; Lead Free Status: Yes; Manufacturer: TDK Electronics; Manufacturer Part Num: CGB2A1X5R1E105K033BC; Num Pins: 2; Part Class: CAPACITORS; RoHS Compliant: Yes; Voltage: 25V
C2003 = CAP: Dielectric: X6S; Item Num: P03-XXXXXR; LIFECYCLE_PHASE: Active; Lead Free Status: Lead Free; Num Pins: 2; Part Class: CAPACITORS; RoHS Compliant: RoHS Compliant; VOLTAGE: 6.3V
C2004 = CAP: CAP CER 360PF 50V U2J 0402; Dielectric: X6S; IPN: M78145-001; IPN No: M78145-001; Item Num: P03-XXXXXR; LIFECYCLE_PHASE: Active; Lead Free Status: Lead Free; Manufacturer: Kemet; Manufacturer Part Num: C0402C361F5JAC7867; Num Pins: 2; Part Class: CAPACITORS; RoHS Compliant: RoHS Compliant; Tolerance: 1%; VOLTAGE: 6.3V
D25 = PMEG2005AEL,315: IPN: H64664-001; IPN No: H64664-001; Manufacturer Part Num: PMEG2005AEL
J17 = 1x3_HDR_TH: 1X3 .100"CENTER HEADER, .145" MIN SOLDER TAIL; IPN: K12462-001; Item Num: P23-38253R; Manufacturer: Samtec
R470 R471 = RES_0_OHM_5%_1_16W_0402_SMD: IPN: H30887-001
R5957 R5968 R5970-R5972 R5975 R6106-R6109 = RESISTOR: RES,10.0K OHMS,1.0%,1/16W, 0402; AGILE_LINK: http://sj-agile9app/Agile/PLMServlet?action=OpenEmailObject&classid=10000&objid=146548997; IPN: A93548-034; Item Num: P02-11364R; LIFECYCLE_PHASE: Active; Lead Free Status: No; MFR_LIFECYCLE: Active; Manufacturer: Panasonic; Manufacturer Part Num: ERJ-2RKF1002X; Num Pins: 2; PART_SUBCLASS: RESISTORS; POWER: 1/16W; RoHS Compliant: Yes; TOLERANCE: +/-1%
R5969 = RESISTOR: RES,10.0K OHMS,1.0%,1/16W, 0402; AGILE_LINK: http://sj-agile9app/Agile/PLMServlet?action=OpenEmailObject&classid=10000&objid=146548997; IPN: A93548-034; Item Num: P02-11364R; LIFECYCLE_PHASE: Active; Lead Free Status: No; MFR_LIFECYCLE: Active; Manufacturer: Panasonic; Manufacturer Part Num: ERJ-2RKF1002X; Num Pins: 2; PART_SUBCLASS: RESISTORS; POWER: 1/16W; RESISTANCE: 10.0K; RoHS Compliant: Yes; TOLERANCE: +/-1%
R5980 = RES_0_OHM_5%_1_16W_0402_SMD: RES 787 OHM 1% 1/16W 0402; IPN: A93548-380; Manufacturer: YAGEO; Manufacturer Part Num: RC0402FR-07787RL
R5981 = RESISTOR: RES SMD 10.7K OHM 1% 1/16W 0402; AGILE_LINK: http://sj-agile9app/Agile/PLMServlet?action=OpenEmailObject&classid=10000&objid=146548997; IPN: A93548-440; Item Num: P02-11364R; LIFECYCLE_PHASE: Active; Lead Free Status: No; MFR_LIFECYCLE: Active; Manufacturer: Vishay Dale; Manufacturer Part Num: CRCW040210K7FKED; Num Pins: 2; PART_SUBCLASS: RESISTORS; POWER: 1/16W; RoHS Compliant: Yes; TOLERANCE: +/-1%
R5982 = RESISTOR: RES - 2.61K OHM, 1%,1/10W, 0402 SMD; AGILE_LINK: http://sj-agile9app/Agile/PLMServlet?action=OpenEmailObject&classid=10000&objid=146548997; IPN: G41697-001; Item Num: P02-11364R; LIFECYCLE_PHASE: Active; Lead Free Status: No; MFR_LIFECYCLE: Active; Manufacturer: YAGEO; Manufacturer Part Num: ERJ-2RKF2611x; Num Pins: 2; PART_SUBCLASS: RESISTORS; POWER: 1/16W; RoHS Compliant: Yes; TOLERANCE: +/-1%
R5983 = RESISTOR: RES SMD 16.2K OHM 1% 1/10W 0402; Altera Part No.: P02-14020R; IPN: K21614-001; Item Num: P02-14020R; Lead Free Status: No; Manufacturer: Panasonic; Manufacturer Part Num: ERJ-2RKF1622X; Num Pins: 2; Part Class: RESISTORS; Price: 0; RoHS Compliant: Yes; Tolerance: 1%
R6098 = RESISTOR: RES 20.0K OHM 1/16W 1% 0402 SMD; IPN: A93548-181; IPN No: A93548-181; Item Num: P02-14071R; Lead Free Status: Yes; Manufacturer: Panasonic; Manufacturer Part Num: ERJ-2RKF2002X; Num Pins: 2; POWER: 1/16W; Part Class: RESISTORS; RoHS Compliant: Yes; Tolerance: ±1%
U71 = LTM4686EV-1#PBF: IC,LIN,PLGA,LTM4686EV-1,CONTROLR; IPN: M75350-001
C1833 C1834 C1848 C1849 C1859 C1860 C1875 C1876 C1987 = Cap,_NP,_0402: CAPC,X6S,0402,1.00UF,25V,+/- 10%; Agile Part Number: 11606; Dielectric: X5R/X6S; IPN: H81594-001; Manufacturer: Murata; Manufacturer Part Num: GRM155C81E105KE11D; Package: 0402; Part Number: GRM155C81E105KE11D; Structure: MLCC; Voltage: 25V
C2039 = Cap,_NP,_0402: CAP CER 4.7UF 10V X5R 0402; Agile Part Number: P03-17662R; Dielectric: X5R; IPN: J29703-001; Item Num: P03-17662R; Manufacturer: TDK Electronics; Manufacturer Part Num: CL05A475KP5NRNC; TOLERANCE: ±10%; Voltage: 10V
R6074 = RES: RES SMD 30.1KOHM 0.1% 1/16W 0402; IPN: E42634-001; Item Num: P02-15992R; Manufacturer: Panasonic; Manufacturer Part Num: ERA-2APB3012X; Package: SMD; Part Class: RESISTORS; Type: Resistor
U70 = LTM4668IY#PBF: IPN: M85055-001
C1835-C1838 C1850-C1853 C1861-C1864 C1877-C1880 = Cap,_NP,_1206: CAPC,X6S,1206,22UF,25V,+/- 10%; Agile Part Number: 06593; Dielectric: X5R/X6S; IPN: H65936-001; Manufacturer Part Num: GRM31CC81E226K; Package: 0805; Part Number: GRM31CC81E226K; Structure: MLCC; Voltage: 25V
C1839 C1995 C1997 C1999 = Cap,_NP,_0402: CAP CER 10UF 10V X5R 0402; Agile Part Number: P03-17662R; Dielectric: X5R; IPN: J40971-001; Item Num: P03-17662R; Manufacturer: Samsung Electro-Mechanics; Manufacturer Part Num: CL05A106MP8NUB8; Part Number: CL05A106MP8NUB8; TOLERANCE: ±10%; Voltage: 10V
C1840 C1994 C1996 C1998 = CAP: CAP, X5R, 1UF, 20%, 10V, 0402,; IPN: H67656-001; Item Num: P03-15479R; Lead Free Status: Yes; Manufacturer: Murata; Manufacturer Part Num: GRM155R61A105KE15D; Num Pins: 2; Part Class: CAPACITORS; RoHS Compliant: Yes; Voltage: 10V
C1841 C1844-C1847 C1856 C1869 C1883 = CAPPOL: CAPS,AL-P,V,470.00uF,2.5V,+/- 20%,V,; IPN: K22160-001; Manufacturer: Panasonic; Manufacturer Part Num: EEFGX0E471R; Package: 2917; Package Size: 2917 (D3L); Part Number: EEFGX0E471R; Voltage: 2.5V
C1842 C1843 C1857 C1858 C1870 C1871 C1884 C1885 C2013-C2015 C2021-C2024 = Cap,_NP,_0805: CAPC,X6S,0805,100.00UF,4.00V,+/-20%; Agile Part Number: DNI; Dielectric: X6S; IPN: H94455-002; Manufacturer: Murata; Manufacturer Part Num: GRM21BC80G107ME15L; Package: 0805; Part Number: GRM21BC80G107ME15L; WVDC: 4V
C2016 = Cap,_NP,_0805: CAPC,X6S,0805,100.00UF,4.00V,+/-20%; Agile Part Number: DNI; Dielectric: X6S; IPN: H94455-002; Manufacturer: Murata; Manufacturer Part Num: GRM21BC80G107ME15L; Package: 0805; Part Number: GRM21BC80G107ME15L; Voltage: 4V; WVDC: 4V
C2017-C2020 C2025 C2027 = CAP: CAP CER 47PF 50V C0G/NP0 0402; AGILE_LINK: http://sj-agile9app/Agile/PLMServlet?action=OpenEmailObject&classid=10000&objid=257560276; IPN: K19455-001; Item Num: P03-17996R; LIFECYCLE_PHASE: Active; Lead Free Status: Not Lead Free; MFR_LIFECYCLE: Active; Manufacturer: Murata; Manufacturer Part Num: GRM1555C1H470FA01D; Num Pins: 2; PART_SUBCLASS: CAPACITORS; RATED_VOLTAGE: 50V; RoHS Compliant: RoHS Compliant; TOLERANCE: 1%; Temperature Coefficient: C0G/NPO; Voltage: 50V
L23-L26 = FP1008R6-R150-R: IPN: K83197-001
R5944 R6087-R6089 = Resistor,_0402_0: RES,1 OHM1/16W 1%0402 SMD; Agile Part Number: 02495; IPN: H50712-001; Manufacturer Part Num: RC0402FR-071RL; Package: 0402; Part Number: RC0402FR-071RL
R5945 R5946 R5951 R5952 R5954 R5955 R5961 R5962 R6110-R6113 = Resistor,_0402_0: RES D,0402,0.00 OHM,5.00%,1/16W; Agile Part Number: 02495; IPN: A93549-001; Manufacturer Part Num: ERJ-2GE0R00X; Package: 0402; Part Number: ERJ-2GE0R00X
R5947 = Resistor,_0402_0: RES 100 OHM 1/16W 1% 0402 SMD; Agile Part Number: 02495; IPN: C51992-001; Manufacturer: PANASONIC; Manufacturer Part Num: ERJ-2RKF1000X; Package: 0402; Part Number: ERJ-2GE0R00X
R5948 = Resistor,_0603_0: Agile Part Number: NEW; IPN: A93550-026; Manufacturer: Yageo; Manufacturer Part Num: RC0603FR-07100RL; Package: 0603; Part Number: RC0603FR-07100RL
R5949 = Resistor,_0402_0: RES 100 OHM 1/16W 1% 0402 SMD; Agile Part Number: 02495; IPN: C51992-001; IPN No: C51992-001; Manufacturer: PANASONIC; Manufacturer Part Num: ERJ-2RKF1000X; Package: 0402; Part Number: ERJ-2GE0R00X
U76-U79 = LTC7051AV#PBF: IPN: M59804-001
C1868 = CAP: CAPC,Y5V,0402,0.1UF,25V,+80/-20%; Dielectric: Y5V; IPN: K13560-001; Item Num: P03-15057R; LIFECYCLE_PHASE: Active; Lead Free Status: Lead Free; MFR_LIFECYCLE: Active; Manufacturer: Murata; Manufacturer Part Num: GRM155F51E104ZA01D; Num Pins: 2; PART_SUBCLASS: CAPACITORS; Part Class: CAPACITORS; RATED_VOLTAGE: 25V; RoHS Compliant: RoHS Compliant; Tolerance: +80%/-20%; Voltage: 25V
C2026 C2028 = CAP: CAP CER 47PF 50V C0G/NP0 0402; AGILE_LINK: http://sj-agile9app/Agile/PLMServlet?action=OpenEmailObject&classid=10000&objid=257560276; IPN: K19455-001; Item Num: P03-17996R; LIFECYCLE_PHASE: Active; Lead Free Status: Not Lead Free; MFR_LIFECYCLE: Active; Manufacturer: Murata; Manufacturer Part Num: GRM1555C1H470FA01D; Num Pins: 2; PART_SUBCLASS: CAPACITORS; RATED_VOLTAGE: 50V; RoHS Compliant: RoHS Compliant; TOLERANCE: 1%; Temperature Coefficient: C0G/NPO
R5956 = res: RESD,0402,5%,1/16W,0; ALT_SYMBOLS: (T:0402_BGA;B:0402_BGA); Checked: YES; Height: 0.4; IPN: A93549-001; MPN: CRCW04020000Z0ED; MPN_alt: RC0402JR-070RL; Manufacturer: Vishay; Manufacturer Part Num: CRCW04020000Z0ED; Mfg_alt: Yageo; Part Type: FIXED; Power: 1/16W; Tolerance: 5%; Datasheet: File:///P:\pcb_lib\datasheets\Resistor\Vishay%20CRCWxxxxxEx%20SMD%20Thick%20Film%20Resistor.pdf
R5958 = Resistor,_0402: RES 215K OHM 1% 1/16W 0402; Agile Part Number: P02-15647R; IPN: K21634-001; Manufacturer: Stackpole Electronics; Manufacturer Part Num: RMCF0402FT215K; Power: 1/16W; TOLERANCE: ±1%
R6078 = Resistor,_0402: RES 4.12K OHM 1% 1/16W 0402; Agile Part Number: P02-15647R; IPN: J18434-001; Manufacturer: Yageo; Manufacturer Part Num: RC0402FR-074K12L; Power: 1/16W; TOLERANCE: ±1%
U124 = LTM4622EV#PBF: IPN: J24671-001

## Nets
5V: C1895.1 R5966.2 R5967.1 ; also on sheet 41 49 63
12V_G1: C1833.1 C1834.1 C1835.2 C1836.2 C1837.2 C1838.2 C1848.1 C1849.1 C1850.2 C1851.2 C1852.2 C1853.2 C1859.1 C1860.1 C1861.2 C1862.2 C1863.2 C1864.2 C1872.2 C1873.1 C1875.1 C1876.1 C1877.2 C1878.2 C1879.2 C1880.2 C2030.2 R5957.2 U76.20(VIN1) U76.21(VIN2) U76.37(VIN3) U76.38(VIN4) U76.43(VIN5) U77.20(VIN1) U77.21(VIN2) U77.37(VIN3) U77.38(VIN4) U77.43(VIN5) U78.20(VIN1) U78.21(VIN2) U78.37(VIN3) U78.38(VIN4) U78.43(VIN5) U79.20(VIN1) U79.21(VIN2) U79.37(VIN3) U79.38(VIN4) U79.43(VIN5) U124.A2(VIN2_1) U124.B3(VIN2_2) U124.D3(VIN1_1) U124.E2(VIN1_2) ; also on sheet 9 12 15 18 47 48 51 58
12V_G2: C1890.1 C1891.2 C1892.2 C1893.2 C1894.2 C1901.2 C1903.2 C1986.2 C1987.1 C2000.2 C2002.2 C2035.2 R5965.1 U51.C5(SVIN) U51.D5(VIN1) U51.E5(VIN2) U70.A4(VIN1) U70.B4(VIN2) U70.F4(VIN3) U70.G4(VIN4) U71.A9(VIN0_1) U71.B9(VIN0_2) U71.C9(VIN0_3) U71.D9(VIN0_4) U71.J9(VIN1_1) U71.K9(VIN1_2) U71.L9(VIN1_3) U71.M9(VIN1_4) ; also on sheet 45 48 49 50 60 61 63 64
GND: C1833.2 C1834.2 C1835.1 C1836.1 C1837.1 C1838.1 C1839.1 C1840.2 C1841.2(n) C1842.1 C1843.1 C1844.2(n) C1845.2(n) C1846.2(n) C1847.2(n) C1848.2 C1849.2 C1850.1 C1851.1 C1852.1 C1853.1 C1856.2(n) C1857.1 C1858.1 C1859.2 C1860.2 C1861.1 C1862.1 C1863.1 C1864.1 C1867.1 C1868.2 C1869.2(n) C1870.1 C1871.1 C1872.1 C1873.2 C1874.1 C1875.2 C1876.2 C1877.1 C1878.1 C1879.1 C1880.1 C1883.2(n) C1884.1 C1885.1 C1886.2 C1887.1 C1888.1 C1889.1 C1890.2 C1891.1 C1892.1 C1893.1 C1894.1 C1895.2 C1896.1 C1897.1 C1898.1 C1899.2 C1900.1 C1903.1 C1905.2 C1906.2 C1907.1 C1908.1 C1910.1 C1911.1 C1912.2 C1913.1 C1986.1 C1987.2 C1988.2 C1989.2 C1994.2 C1995.1 C1996.2 C1997.1 C1998.2 C1999.1 C2000.1 C2002.1 C2013.1 C2014.1 C2015.1 C2016.1 C2017.1 C2018.2 C2019.2 C2020.1 C2021.1 C2022.1 C2023.1 C2024.1 C2025.2 C2026.1 C2027.2 C2028.1 C2029.1 C2030.1 C2035.1 C2039.1 J17.3 R5948.1 R5949.1 R5956.1 R5958.2 R5978.1 R5991.1 R5998.2 R6073.1 R6077.1 R6078.2 R6102.2 ST3.2 ST16.2 ST19.2 ST20.2 U51.B3(GND) U51.C3(GND) U51.D3(GND) U51.D4(GND) U51.E3(GND) U65.A1(GND) U65.A2(GND) U65.A3(GND) U65.A4(GND) U65.A5(GND) U65.A6(GND) U65.A7(GND) U65.A8(GND) U65.A9(GND) U65.A10(GND) U65.A11(GND) U65.B1(GND) U65.B9(GND) U65.B10(GND) U65.B11(GND) U65.F3(GND) U65.F7(GND) U65.F8(GND) U65.G1(GND) U65.G2(GND) U65.G3(GND) U65.G4(GND) U65.G5(GND) U65.G6(GND) U65.G7(GND) U65.G8(GND) U70.A2(GND) U70.A3(GND) U70.A5(GND) U70.A6(GND) U70.B2(GND) U70.B3(GND) U70.B5(GND) U70.B6(GND) U70.C2(GND) U70.C6(GND) U70.D3(GND) U70.D4(GND) U70.D5(GND) U70.E2(GND) U70.E6(GND) U70.F2(GND) U70.F3(GND) U70.F5(GND) U70.F6(GND) U70.G2(GND) U70.G3(GND) U70.G5(GND) U70.G6(GND) U71.A2(GND) U71.A3(GND) U71.A4(GND) U71.A5(GND) U71.A6(GND) U71.A7(GND) U71.A8(GND) U71.B2(GND) U71.B3(GND) U71.B4(GND) U71.B5(GND) U71.B6(GND) U71.B7(GND) U71.C2(GND) U71.C4(GND) U71.C5(GND) U71.C6(GND) U71.C7(GND) U71.C8(GND) U71.D2(GND) U71.D5(GND) U71.E1(GND) U71.E9(GND) U71.F1(GND) U71.F8(GND) U71.G1(GND) U71.G8(GND) U71.G9(GND) U71.H1(GND) U71.H8(GND) U71.H9(GND) U71.J2(GND) U71.J8(GND) U71.K2(GND) U71.K5(GND) U71.K6(GND) U71.K7(GND) U71.K8(GND) U71.L2(GND) U71.L3(GND) U71.L4(GND) U71.L5(GND) U71.L6(GND) U71.L7(GND) U71.M2(GND) U71.M3(GND) U71.M4(GND) U71.M5(GND) U71.M6(GND) U71.M7(GND) U71.M8(GND) U76.7(PGND) U76.8(PGND) U76.9(PGND) U76.17(PGND) U76.18(PGND) U76.19(PGND) U76.27(PGND) U76.31(SGND) U76.39(PGND) U76.40(PGND) U76.41(PGND) U77.7(PGND) U77.8(PGND) U77.9(PGND) U77.17(PGND) U77.18(PGND) U77.19(PGND) U77.27(PGND) U77.31(SGND) U77.39(PGND) U77.40(PGND) U77.41(PGND) U78.7(PGND) U78.8(PGND) U78.9(PGND) U78.17(PGND) U78.18(PGND) U78.19(PGND) U78.27(PGND) U78.31(SGND) U78.39(PGND) U78.40(PGND) U78.41(PGND) U79.7(PGND) U79.8(PGND) U79.9(PGND) U79.17(PGND) U79.18(PGND) U79.19(PGND) U79.27(PGND) U79.31(SGND) U79.39(PGND) U79.40(PGND) U79.41(PGND) U124.B5(GND) U124.C1(GND) U124.C2(GND) U124.D5(GND) ; also on sheet 9 11 12 13 14 15 17 18 20 21 22 23 24 25 26 28 29 30 31 32 34 35 36 37 38 39 40 41 42 43 44 45 46 47 48 49 50 51 58 59 60 61 62 63 64 65 66
PVCC: C1839.2 C1867.2 C1868.1 C1995.2 C1997.2 C1999.2 C2029.2 C2031.2 R5944.2 R6087.2 R6088.2 R6089.2 U76.28(PVCC) U76.29(PVCC) U77.28(PVCC) U77.29(PVCC) U78.28(PVCC) U78.29(PVCC) U79.28(PVCC) U79.29(PVCC) U124.A1(VOUT2_1) U124.B1(VOUT2_2) U124.D1(VOUT1_2) U124.E1(VOUT1_1)
SVIN1: U65.E5(TRACK) U65.F4(SVIN)
VCC_SENSE: R5947.2 ; also on sheet 33 51
VCCL_HPS_AGND: R5999.1 R6001.1 R6091.2 ST16.1 U65.E1(SGND) U65.F5(ITHM)
VCCL_HPS_EN: R5997.1 ; also on sheet 46
VCCL_HPS_MGN: R6000.1 R6001.2 U65.B8(MGN)
VCCL_HPS_PG: R5994.1 U65.C7(PGOOD) ; also on sheet 46
VCCL_SDM_EN: R5990.2 ; also on sheet 46
VCCL_SDM_PG: R5984.1 U51.C2(PGOOD) ; also on sheet 46
VDD25OUT: TP47.1 U71.J4(VDD25)
VSS_SENSE: R5949.2 ; also on sheet 33 51
0p8V_AGND: C1901.1 C1902.1 C1904.1 R5988.1 R5993.1 ST3.1 U51.B4(SGND)
0p8V_VCCL_SDM: C1905.1 C1906.1 C2032.2 U51.C1(VOUT1) U51.D1(VOUT2) U51.D2(VOUT3) U51.E1(VOUT4) U51.E2(VOUT5) ; also on sheet 34 46 65
0p9V_VCCL_HPS: C1909.1 C1910.2 C1911.2 C1912.1 C1913.2 U65.C10(VOUT1) U65.C11(VOUT2) U65.D10(VOUT3) U65.D11(VOUT4) U65.E9(VOUT5) U65.E10(VOUT6) U65.E11(VOUT7) U65.F9(VOUT8) U65.F10(VOUT9) U65.F11(VOUT10) U65.G9(VOUT11) U65.G10(VOUT12) U65.G11(VOUT13) ; also on sheet 34 46 65
1p8V: C1886.1 C1887.2 C1888.2 C1889.2 C1896.2 C1897.2 C1898.2 C1899.1 R5963.1 U71.A1(VOUT0_1) U71.B1(VOUT0_2) U71.C1(VOUT0_3) U71.D1(VOUT0_4) U71.J1(VOUT1_1) U71.K1(VOUT1_2) U71.L1(VOUT1_3) U71.M1(VOUT1_4) ; also on sheet 22 34 46 65
1p8V_AGND: C2003.1 R5975.1 R5980.2 R5981.1 R5982.1 R5983.1 R6098.1 ST19.1 U71.F5(SGND) U71.F6(SGND) U71.G5(SGND) U71.G6(SGND)
1p8V_EN: R5977.2 ; also on sheet 46
3p3V: C1907.2 C1908.2 R5968.2 R5969.2 R5970.2 R5971.2 R5972.2 R5973.1 R5984.2 R5989.2 R5994.2 R5995.1 R6000.2 R6071.2 R6075.2 R6274.1 R6275.1 U65.C1(VIN1) U65.C8(VIN2) U65.C9(VIN3) U65.D1(VIN4) U65.D3(VIN5) U65.D4(VIN6) U65.D5(VIN7) U65.D7(VIN8) U65.D8(VIN9) U65.D9(VIN10) U65.E8(VIN11) ; also on sheet 46 50 51 58 59 60 61 62 63 64
COMPA_1P8V: C2003.2 C2004.2 R6103.1 R6104.1
FAULT: R6110.1 R6111.1 R6112.1 R6113.1 ; also on sheet 51
FPGA_VCC: C1841.1(p) C1842.2 C1843.2 C1844.1(p) C1845.1(p) C1846.1(p) C1847.1(p) C1856.1(p) C1857.2 C1858.2 C1869.1(p) C1870.2 C1871.2 C1883.1(p) C1884.2 C1885.2 C2013.2 C2014.2 C2015.2 C2016.2 C2021.2 C2022.2 C2023.2 C2024.2 L23.2 L24.2 L25.2 L26.2 R5947.1 R5948.2 ; also on sheet 33 46 65 66
INTVCC_PVCC: R5960.2 U124.C3(INTVCC)
IO_1p8V: C1988.1 C1989.1 C2034.1 U70.A1(VOUT1_1) U70.A7(VOUT2_1) U70.B1(VOUT1_2) U70.B7(VOUT2_2) U70.F1(VOUT4_1) U70.F7(VOUT3_1) U70.G1(VOUT4_2) U70.G7(VOUT3_2) ; also on sheet 26 28 29 30 31 34 38 39 40 46 65
IO_1p8V_AGND: R6074.1 ST20.1
IO_1p8V_EN: R6076.2 ; also on sheet 46
IO_1p8V_PG: R6071.1 U70.D2(PGOOD1) ; also on sheet 46
ISENSE0: U76.33(ISNS) ; also on sheet 51
ISENSE2: U78.33(ISNS) ; also on sheet 51
ISENSE3: U79.33(ISNS) ; also on sheet 51
ISENSE4: U77.33(ISNS) ; also on sheet 51
LTM4623_INTVCC0: C1900.2 R6096.1 U51.E4(INTVCC)
LTM4668_INTVCC0: C2039.2 R6072.2 U70.C4(INTVCC) U70.C7(FB2) U70.E1(FB4) U70.E7(FB3)
LTM4686_3p3V_PG: D25.1(K) ; also on sheet 46
LTM_PMBUS_ALERTn: R5974.2 ; also on sheet 43 46 58
LTM_SCL: J17.1 R470.2 R6274.2 U71.E4(SCL) ; also on sheet 50 58
LTM_SDA: J17.2 R471.2 R6275.2 U71.D4(SDA) ; also on sheet 50 58
MAIN_I2C_SCL: R470.1 ; also on sheet 38 39 40 44 46 47
MAIN_I2C_SDA: R471.1 ; also on sheet 38 39 40 44 46 47
MODE/SYNC: R6072.1 R6073.2 U70.E4(MODE/SYNC)
PWM0: R5946.1 ; also on sheet 51
PWM2: R5955.1 ; also on sheet 51
PWM3: R5962.1 ; also on sheet 51
PWM4: R5952.1 ; also on sheet 51
RUN0: C1840.1 R5944.1 R6108.2 U76.30(VCC)
RUN2: C1996.1 R6088.1 R6107.2 U78.30(VCC)
RUN3: C1998.1 R6089.1 R6106.2 U79.30(VCC)
RUN4: C1994.1 R6087.1 R6109.2 U77.30(VCC)
SW_U76_FPGA_VCC: L23.1 U76.1(SW1) U76.2(SW1) U76.3(SW1) U76.4(SW1) U76.5(SW1) U76.6(SW1) U76.10(SW2_1) U76.11(SW2_2) U76.12(SW2_3) U76.13(SW2_4) U76.14(SW2_5) U76.15(SW2_6) U76.16(SW2_7) U76.42(SW1_7)
SW_U77_FPGA_VCC: L24.1 U77.1(SW1) U77.2(SW1) U77.3(SW1) U77.4(SW1) U77.5(SW1) U77.6(SW1) U77.10(SW2_1) U77.11(SW2_2) U77.12(SW2_3) U77.13(SW2_4) U77.14(SW2_5) U77.15(SW2_6) U77.16(SW2_7) U77.42(SW1_7)
SW_U78_FPGA_VCC: L25.1 U78.1(SW1) U78.2(SW1) U78.3(SW1) U78.4(SW1) U78.5(SW1) U78.6(SW1) U78.10(SW2_1) U78.11(SW2_2) U78.12(SW2_3) U78.13(SW2_4) U78.14(SW2_5) U78.15(SW2_6) U78.16(SW2_7) U78.42(SW1_7)
SW_U79_FPGA_VCC: L26.1 U79.1(SW1) U79.2(SW1) U79.3(SW1) U79.4(SW1) U79.5(SW1) U79.6(SW1) U79.10(SW2_1) U79.11(SW2_2) U79.12(SW2_3) U79.13(SW2_4) U79.14(SW2_5) U79.15(SW2_6) U79.16(SW2_7) U79.42(SW1_7)
TMON0: C2017.2 R5945.1 U76.22(TMON)
TMON2: C2026.2 R5954.1 U78.22(TMON)
TMON3: C2028.2 R5961.1 U79.22(TMON)
TMON4: C2020.2 R5951.1 U77.22(TMON)
TSNS0: R5945.2 R5951.2 R5954.2 R5961.2 ; also on sheet 51
VOSNS0_1P8V: R5963.2 U71.D7(VOSNS0+) U71.H7(VOSNS1)
N40865174: R5946.2 U76.35(PWM)
N40865834: R5952.2 U77.35(PWM)
N40873145: R5955.2 U78.35(PWM)
N40873851: R5962.2 U79.35(PWM)
N40878568: U71.J3(TSNS1A) U71.K3(TSNS1B)
N40878578: R5964.1 R6104.2 U71.H6(COMP1A)
N40878702: R5964.2 U71.J6(COMP1B)
N40878910: R5965.2 R5967.2 U71.F9(SVIN)
N40878945: R5966.1 U71.F7(INTVCC1) U71.G7(INTVCC2)
N40878955: TP29.1(TP) U71.J5(VDD33)
N40879078: R5968.1 U71.E5(SYNC)
N40879082: R5970.1 U71.H5(SHARE_CLK)
N40879084: R5971.1 U71.F2(~{GPIO1})
N40879086: R5969.1 R5974.1 U71.E3(~{ALERT})
N40879090: D25.2(A) R5972.1 U71.E2(~{GPIO0})
N40879092: R5973.2 R5977.1 R5978.2 U71.F3(RUN0) U71.F4(RUN1)
N40879148: U71.C3(TSNS0_1) U71.D3(TSNS0_2)
N40879172: R5975.2 U71.K4(WP)
N40879270: R6102.1 U71.E7(VOSNS0-)
N40879274: R5980.1 U71.G2(ASEL)
N40879310: R5981.2 U71.H2(FSWPHCFG)
N40879329: R5982.2 U71.G3(VOUT0CFG) U71.G4(VOUT1CFG)
N40879333: R5983.2 U71.H3(VTRIM0CFG) U71.H4(VTRIM1CFG)
N40882065: TP30.1 U51.B5(CLKOUT)
N40882112: TP31.1 U51.A5(CLKIN)
N40882148: R5985.2 R5986.2 R5987.2 R6096.2
N40882229: C1902.2 R5985.1 U51.A1(COMP)
N40882256: R5986.1 U51.B2(PHMODE)
N40882276: R5987.1 U51.C4(MODE)
N40882304: R5988.2 U51.A4(FREQ)
N40882322: C1904.2 U51.A2(TRACK/SS)
N40882328: R5989.1 R5990.1 R5991.2 U51.A3(RUN)
N40882423: C2032.1 R5992.2 U51.B1(FB)
N40882447: R5992.1 R5993.2
N40885340: R5995.2 R5997.2 R5998.1 U65.F1(RUN)
N40885465: C1909.2 R5996.2 U65.E7(FB)
N40885526: TP32.1(TP) U65.B3(CLKIN)
N40885555: TP33.1(TP) U65.F2(CLKOUT)
N40885593: R5999.2 U65.B5(MODE)
N40968297: C2034.2 R6074.2 U70.C1(FB1)
N40969501: R6075.1 R6076.1 R6077.2 U70.C3(RUN1) U70.C5(RUN2) U70.E3(RUN4) U70.E5(RUN3)
N40987662: R5960.1 TP28.1 U124.B4(PGOOD2) U124.D4(PGOOD1)
N40987771: U124.A5(COMP2) U124.E5(COMP1)
N40987783: C2031.1 R6078.1 U124.A4(FB2) U124.E4(FB1)
N40989537: R5957.1 U124.B2(RUN2) U124.D2(RUN1)
N40990671: R5958.1 U124.C4(FREQ)
N40992497: C1874.2 U124.A3(TRACK_SS2) U124.E3(TRACK_SS1)
N40993869: R5956.2 U124.C5(SYNC_MODE)
N41419088: R5976.1 R6103.2 U71.E6(COMP0A)
N41419100: R5976.2 U71.D6(COMP0B)
N41577579: C2018.1 U76.36(TDIO)
N41579874: C2019.1 U77.36(TDIO)
N41584176: C2025.1 U78.36(TDIO)
N41584715: C2027.1 U79.36(TDIO)
N41681478: C2004.1 R6098.2
N41873307: R5996.1 R6091.1
N42039861: R6106.1 U79.32(RUN)
N42039972: R6107.1 U78.32(RUN)
N42040021: R6108.1 U76.32(RUN)
N42040083: R6109.1 U77.32(RUN)
N42040125: R6110.2 U77.34(FLTB)
N42040156: R6111.2 U76.34(FLTB)
N42040187: R6112.2 U78.34(FLTB)
N42040218: R6113.2 U79.34(FLTB)

Not connected (* = marked no-connect by the designer): U65 B4(PHMODE)* B7(BSEL)* C3(SW_1)* C4(SW_2)* C5(SW_3)* E3(PLLLPF)* F6(ITH)*; U70 D1(PGOOD4)* D6(PGOOD2)* D7(PGOOD3)*; U71 B8(SW0)* D8(VORB0+)* E8(VORB0-)* J7(VORB1)* L8(SW1)*; U76 23(NC4)* 24(NC3)* 25(NC2)* 26(NC1)*; U77 23(NC4)* 24(NC3)* 25(NC2)* 26(NC1)*; U78 23(NC4)* 24(NC3)* 25(NC2)* 26(NC1)*; U79 23(NC4)* 24(NC3)* 25(NC2)* 26(NC1)*

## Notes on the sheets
sheet 52
- VCC Core   Phase 1 - 2
- NOTE: Part Attributes of
  components on this page may not
  match up to the component's
  manufacturer's part number!
- TMON OUTPUT: 8mV/°C
- VCC Core (0.8V)
- PHASE 1
- FPGA_VCC = 0.8V @ 121.713A
- VCC Core (0.8V)
- PHASE 2
sheet 53
- VCC Core   Phase 3 - 4
- NOTE: Part Attributes of
  components on this page may not
  match up to the component's
  manufacturer's part number!
- TMON OUTPUT: 8mV/°C
- VCC Core (0.8V)
- PHASE 3
- FSW = 2.5MHz
- VCC Core (0.8V)
- PHASE 4
sheet 54
- PWR - 1p8V
- 1.8V @ 4.506A
- Sense line place near to the load
- NOTE: U71 Default configured for LTM4686EV-1 uModule
  If Changing to LTM4686EV
  UnMount R5966,R5967 AND mount R5965
- VIN  : 12V
- VOUT : 1V8
- Tj   : -40 C TO 125 C
- ILOAD : 4.506A
- I2C ADDR = 41h
- FSW  : 750KHz
- (Top Side 30mil pad,
  No Via)
- 5V Should be up before
  this rail is enabled.
- Sense line place near to the load
- I2C ADDR = 41h
- FSW  : 750KHz
- NOTE:PLACE THESE RESISTORS NEAR TO IC.
- LTM Dongle
- AGND
- PGND
sheet 55
- PWR - 0p8V_VCCL_SDM
- VIN  : 12V
- VOUT : 0p8V
- FSW  : 1MHz
- Tj   : -40 C TO 125 C
- ILOAD :0.332A
- RFB=60.4K x (0.6/Vout-06)
- X5R
- X5R
- 1206
- 1206
- Connect the input
  cap to the GND plane
  through multiple vias.
  (see the Gerber files)
- 0.332A
- Connect the output
  cap to the GND plane
  through multiple vias
- AGND
- PGND
- PLACE Output decoupling caps
  close to the device.  Connect
  AGND and PGND at the point of
  cap GND connection.
sheet 56
- PWR- 0p9V_VCCL_HPS
- 3.77A
- VIN  : 3p3V
- VOUT : 0p9V
- FSW  : 1.5MHz CCM
- Tj   : -40 C TO 125 C
- ILOAD : 3.77A
- VOUT : 0.596 * (10K+19.599K/19.599K)
- ~100µs of internal soft-start during start-up
  MGN : DISABLED
- AGND
- PGND
sheet 57
- PWR - IO_1p8V
- Connect the input
  cap to the GND plane
  through multiple vias.
- Connect the output
  cap to the GND plane
  through multiple vias
- VIN  : 12V
- VOUT : 1p8V
- FSW  : 1 MHz
- AGND
- Tj   : -40 C TO 125 C
- ILOAD : 4A
- PLACE Output decoupling caps
  close to the device.  Connect
  AGND and PGND at the point of
  cap GND connection.
- RFB=60.4K x (0.6/Vout-06)
